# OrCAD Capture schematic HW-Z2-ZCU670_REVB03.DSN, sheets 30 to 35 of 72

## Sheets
30 030 FMC HSPC3: size Custom
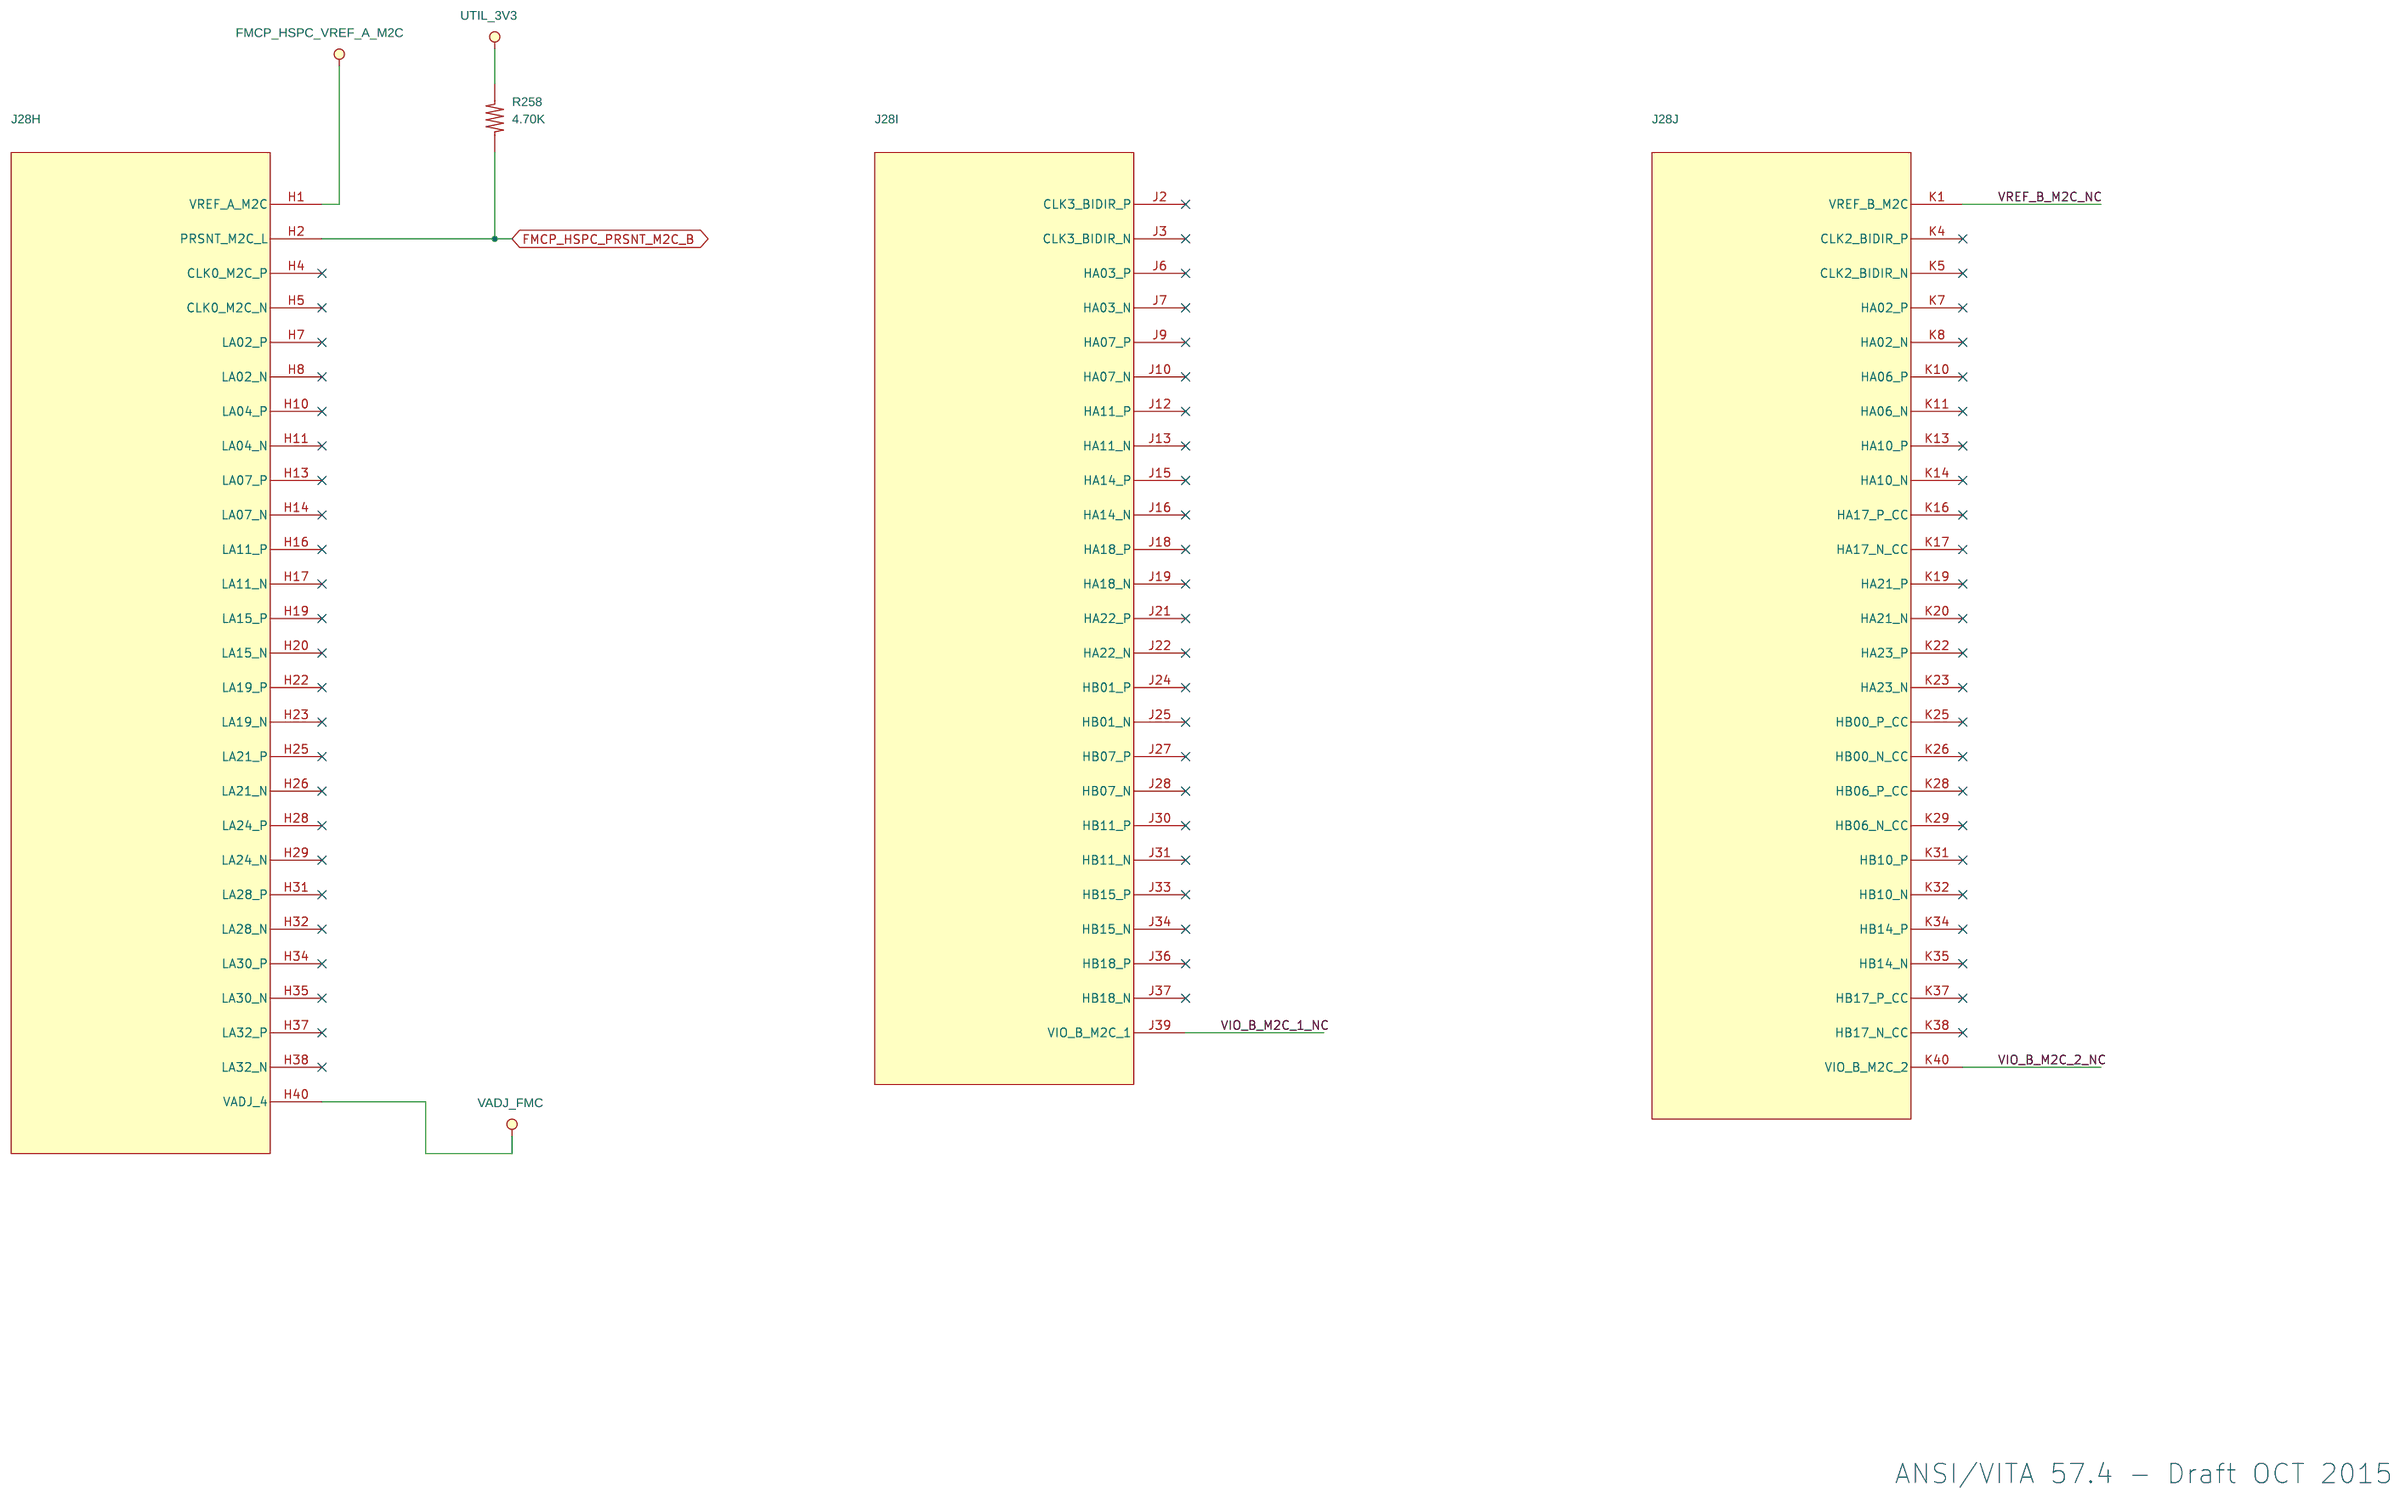
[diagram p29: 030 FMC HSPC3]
31 031 FMC HSPC4: size Custom
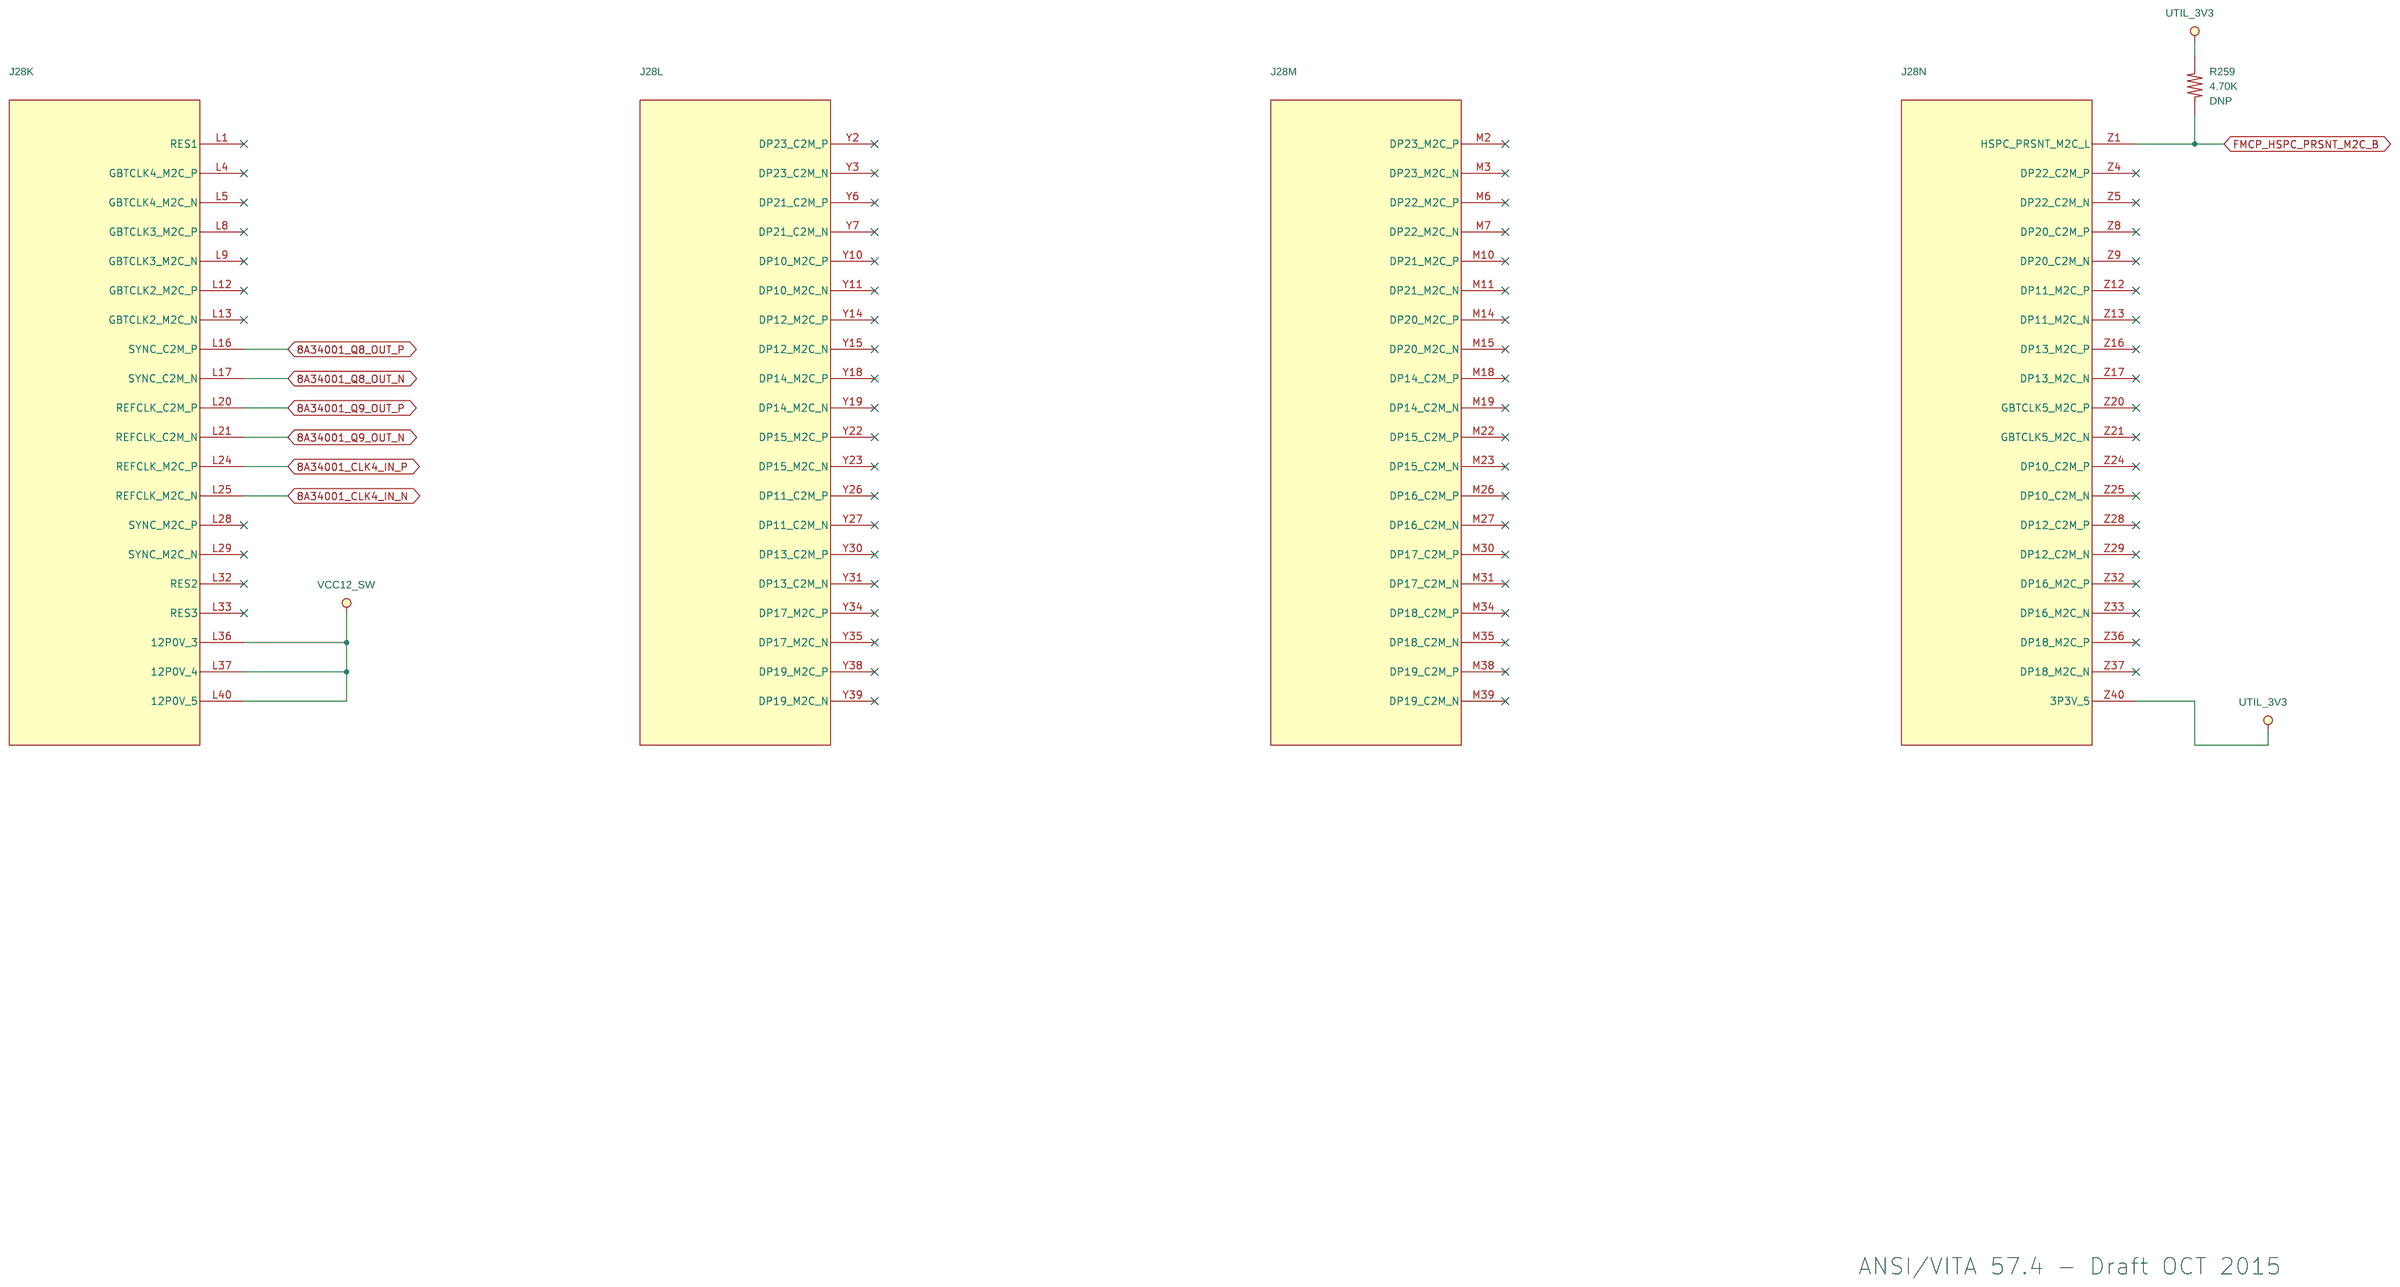
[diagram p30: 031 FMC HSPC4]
32 032 FMC HSPC5: size Custom
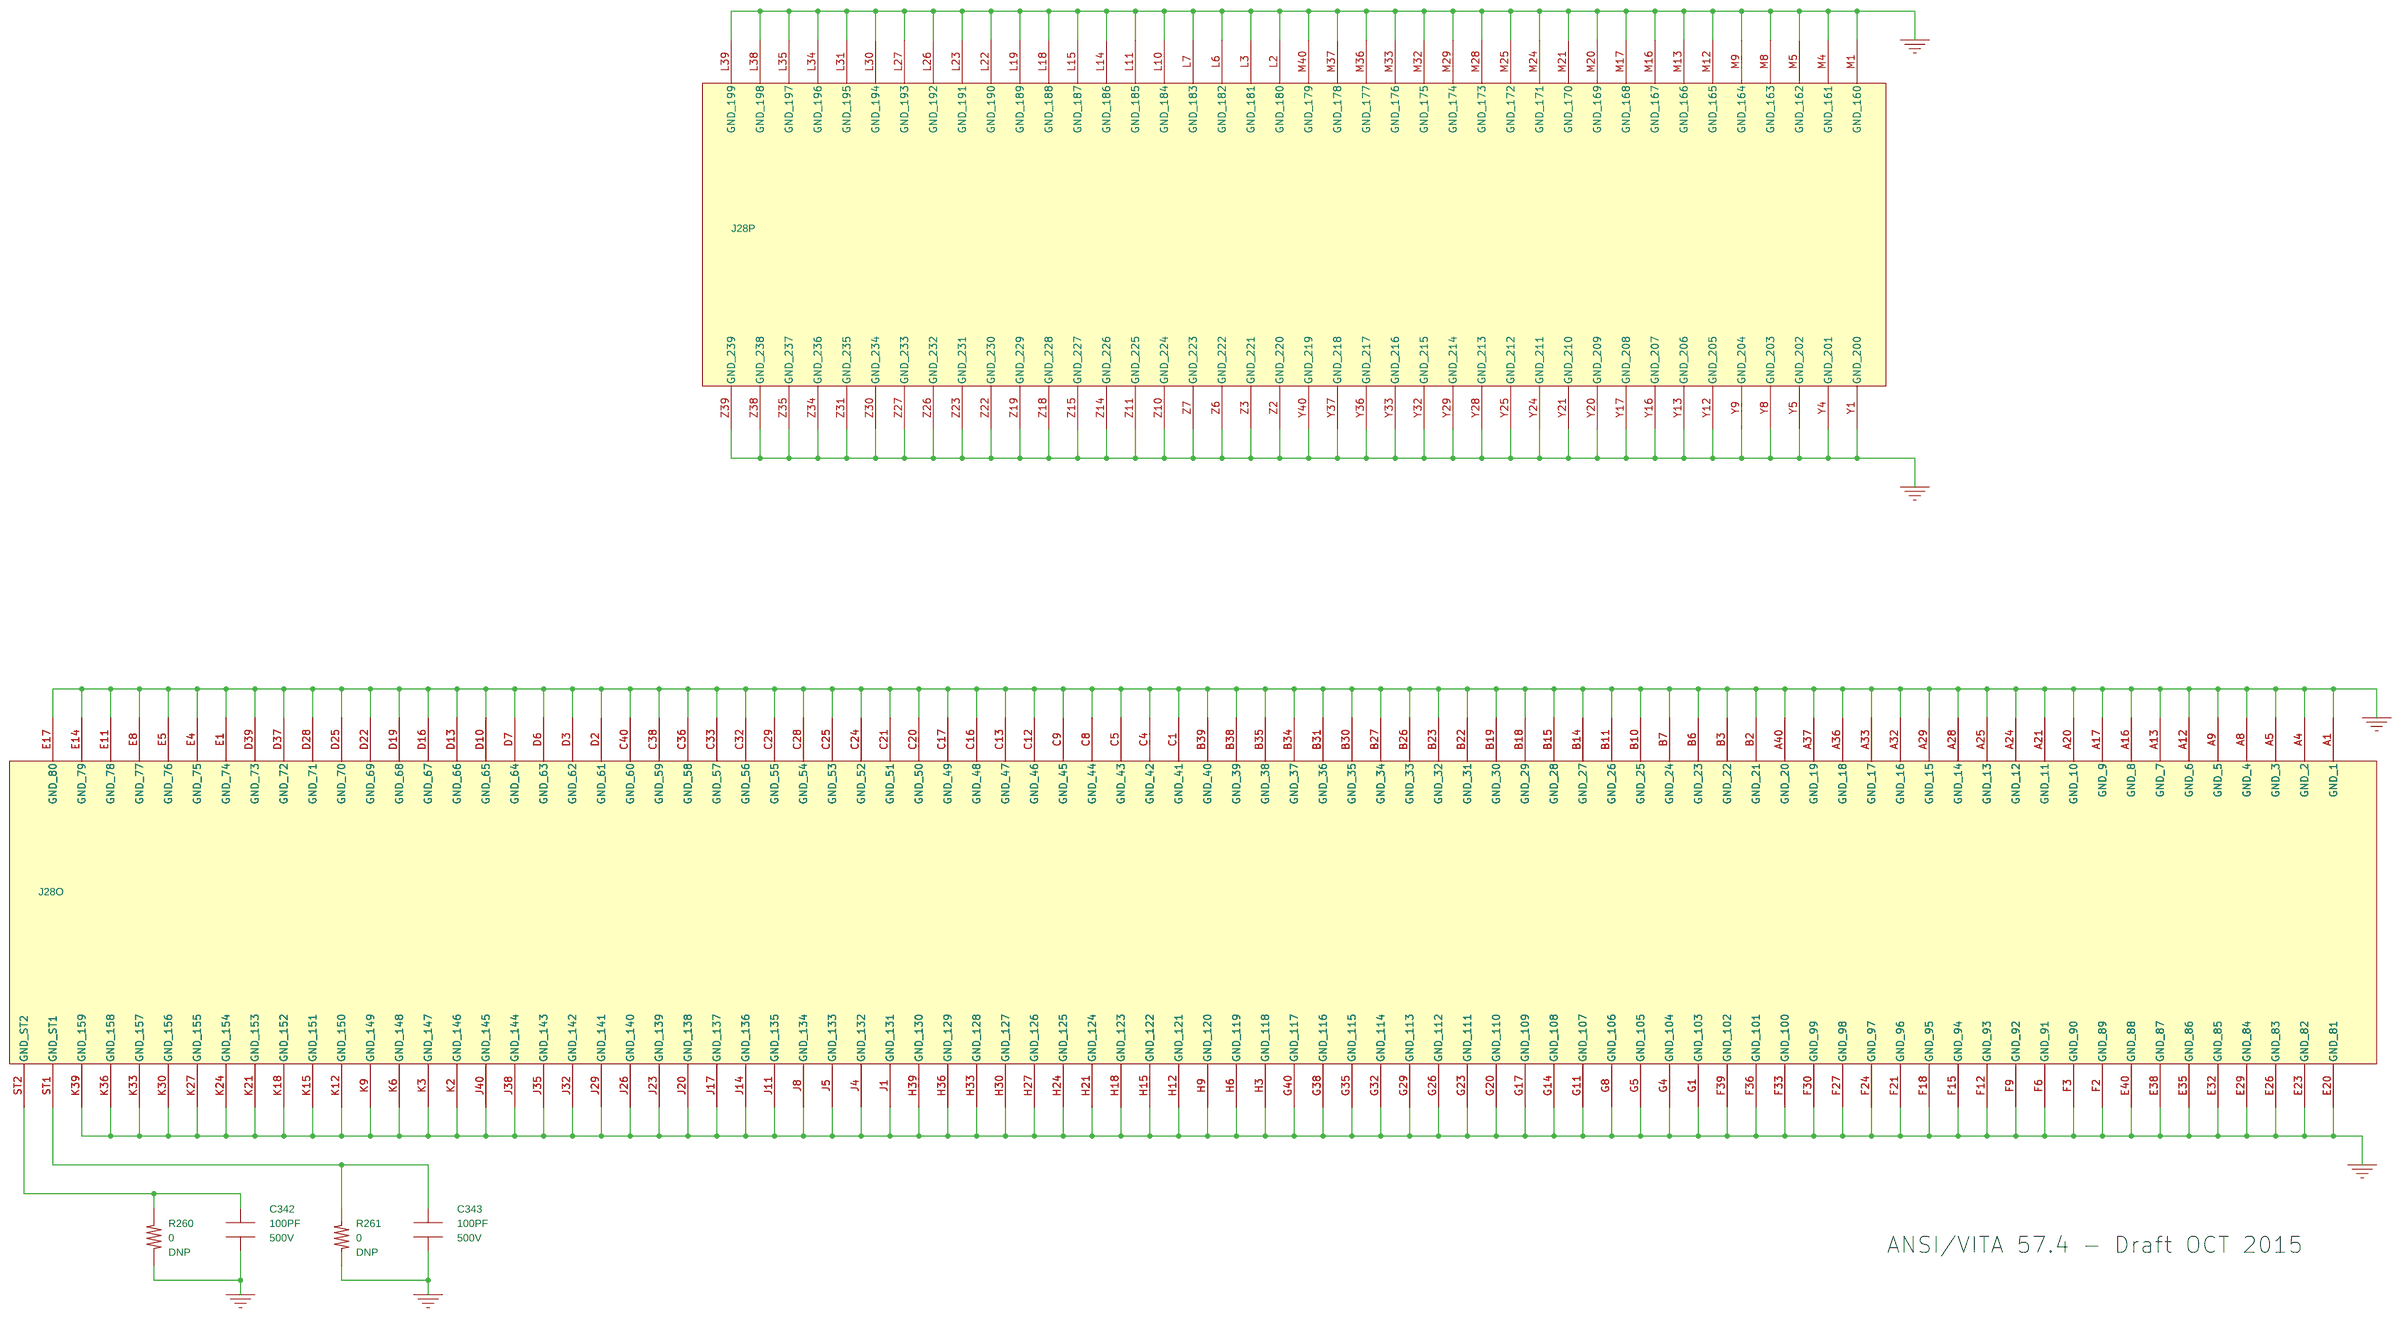
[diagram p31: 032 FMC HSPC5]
33 033 zSFP 2x2 Connector: size Custom
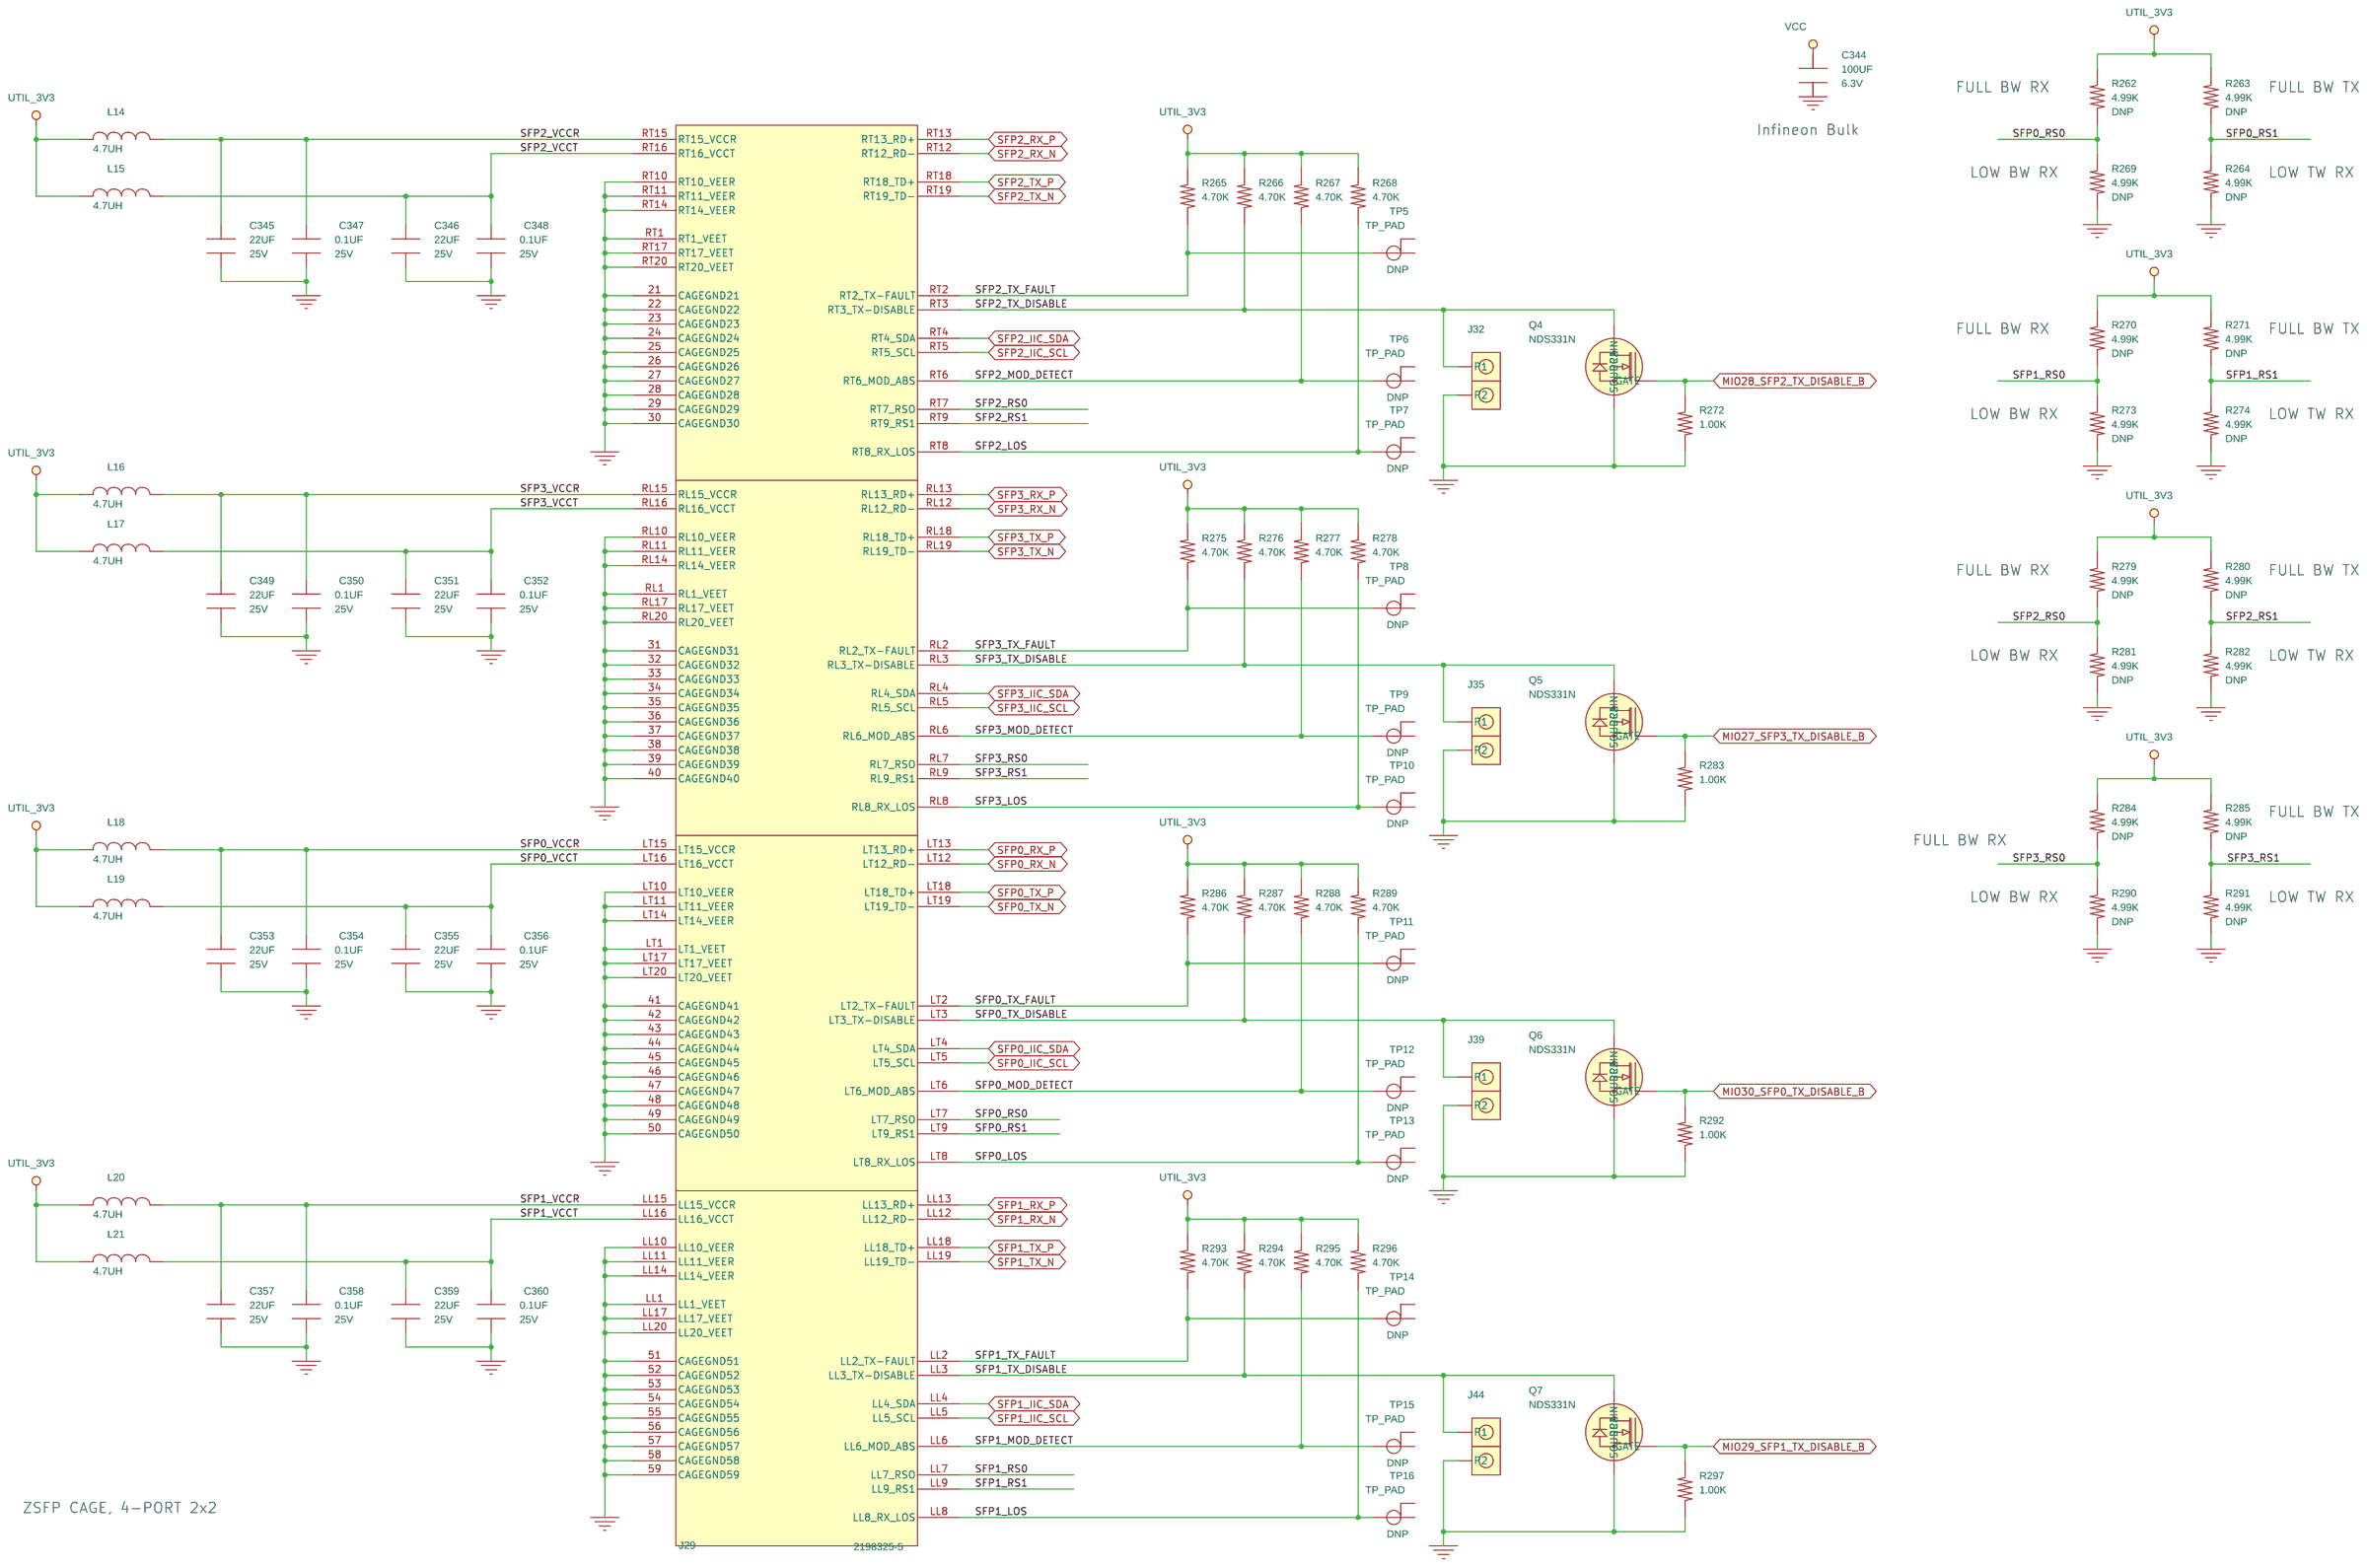
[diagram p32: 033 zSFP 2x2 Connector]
34 034 1588 eCPRI CLK 1: size Custom
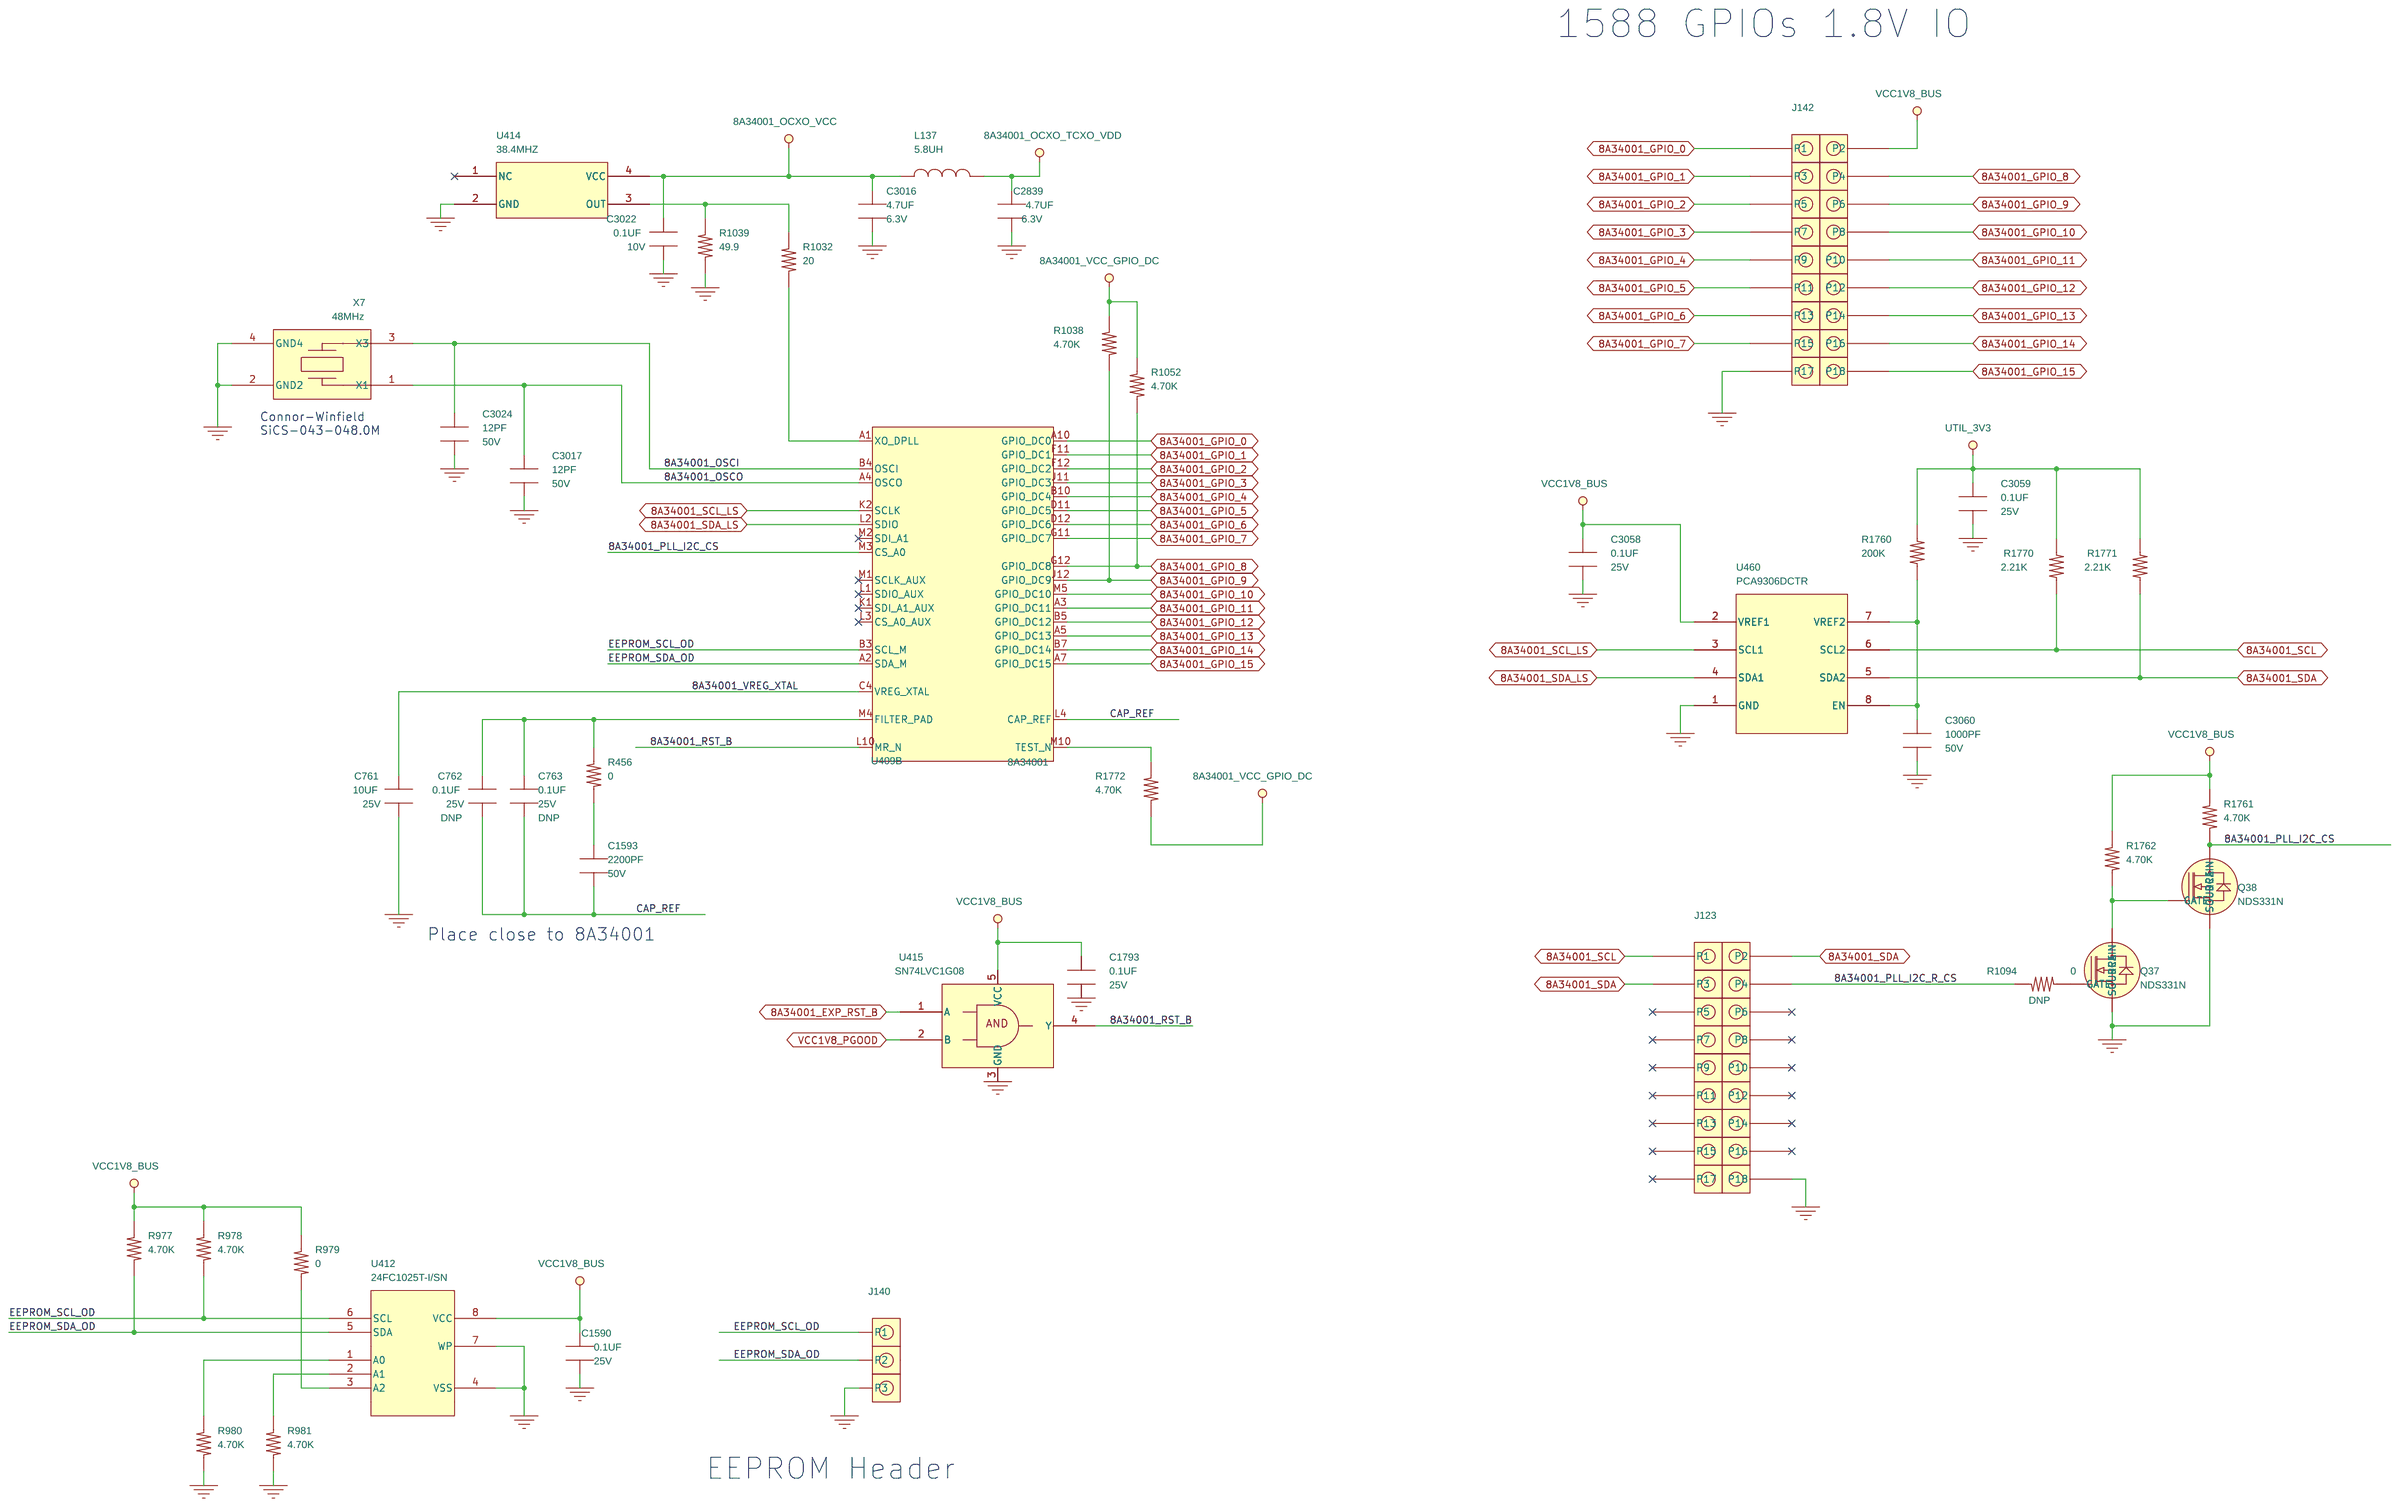
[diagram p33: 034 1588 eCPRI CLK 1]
35 036 1588 eCPRI CLK 3: size Custom
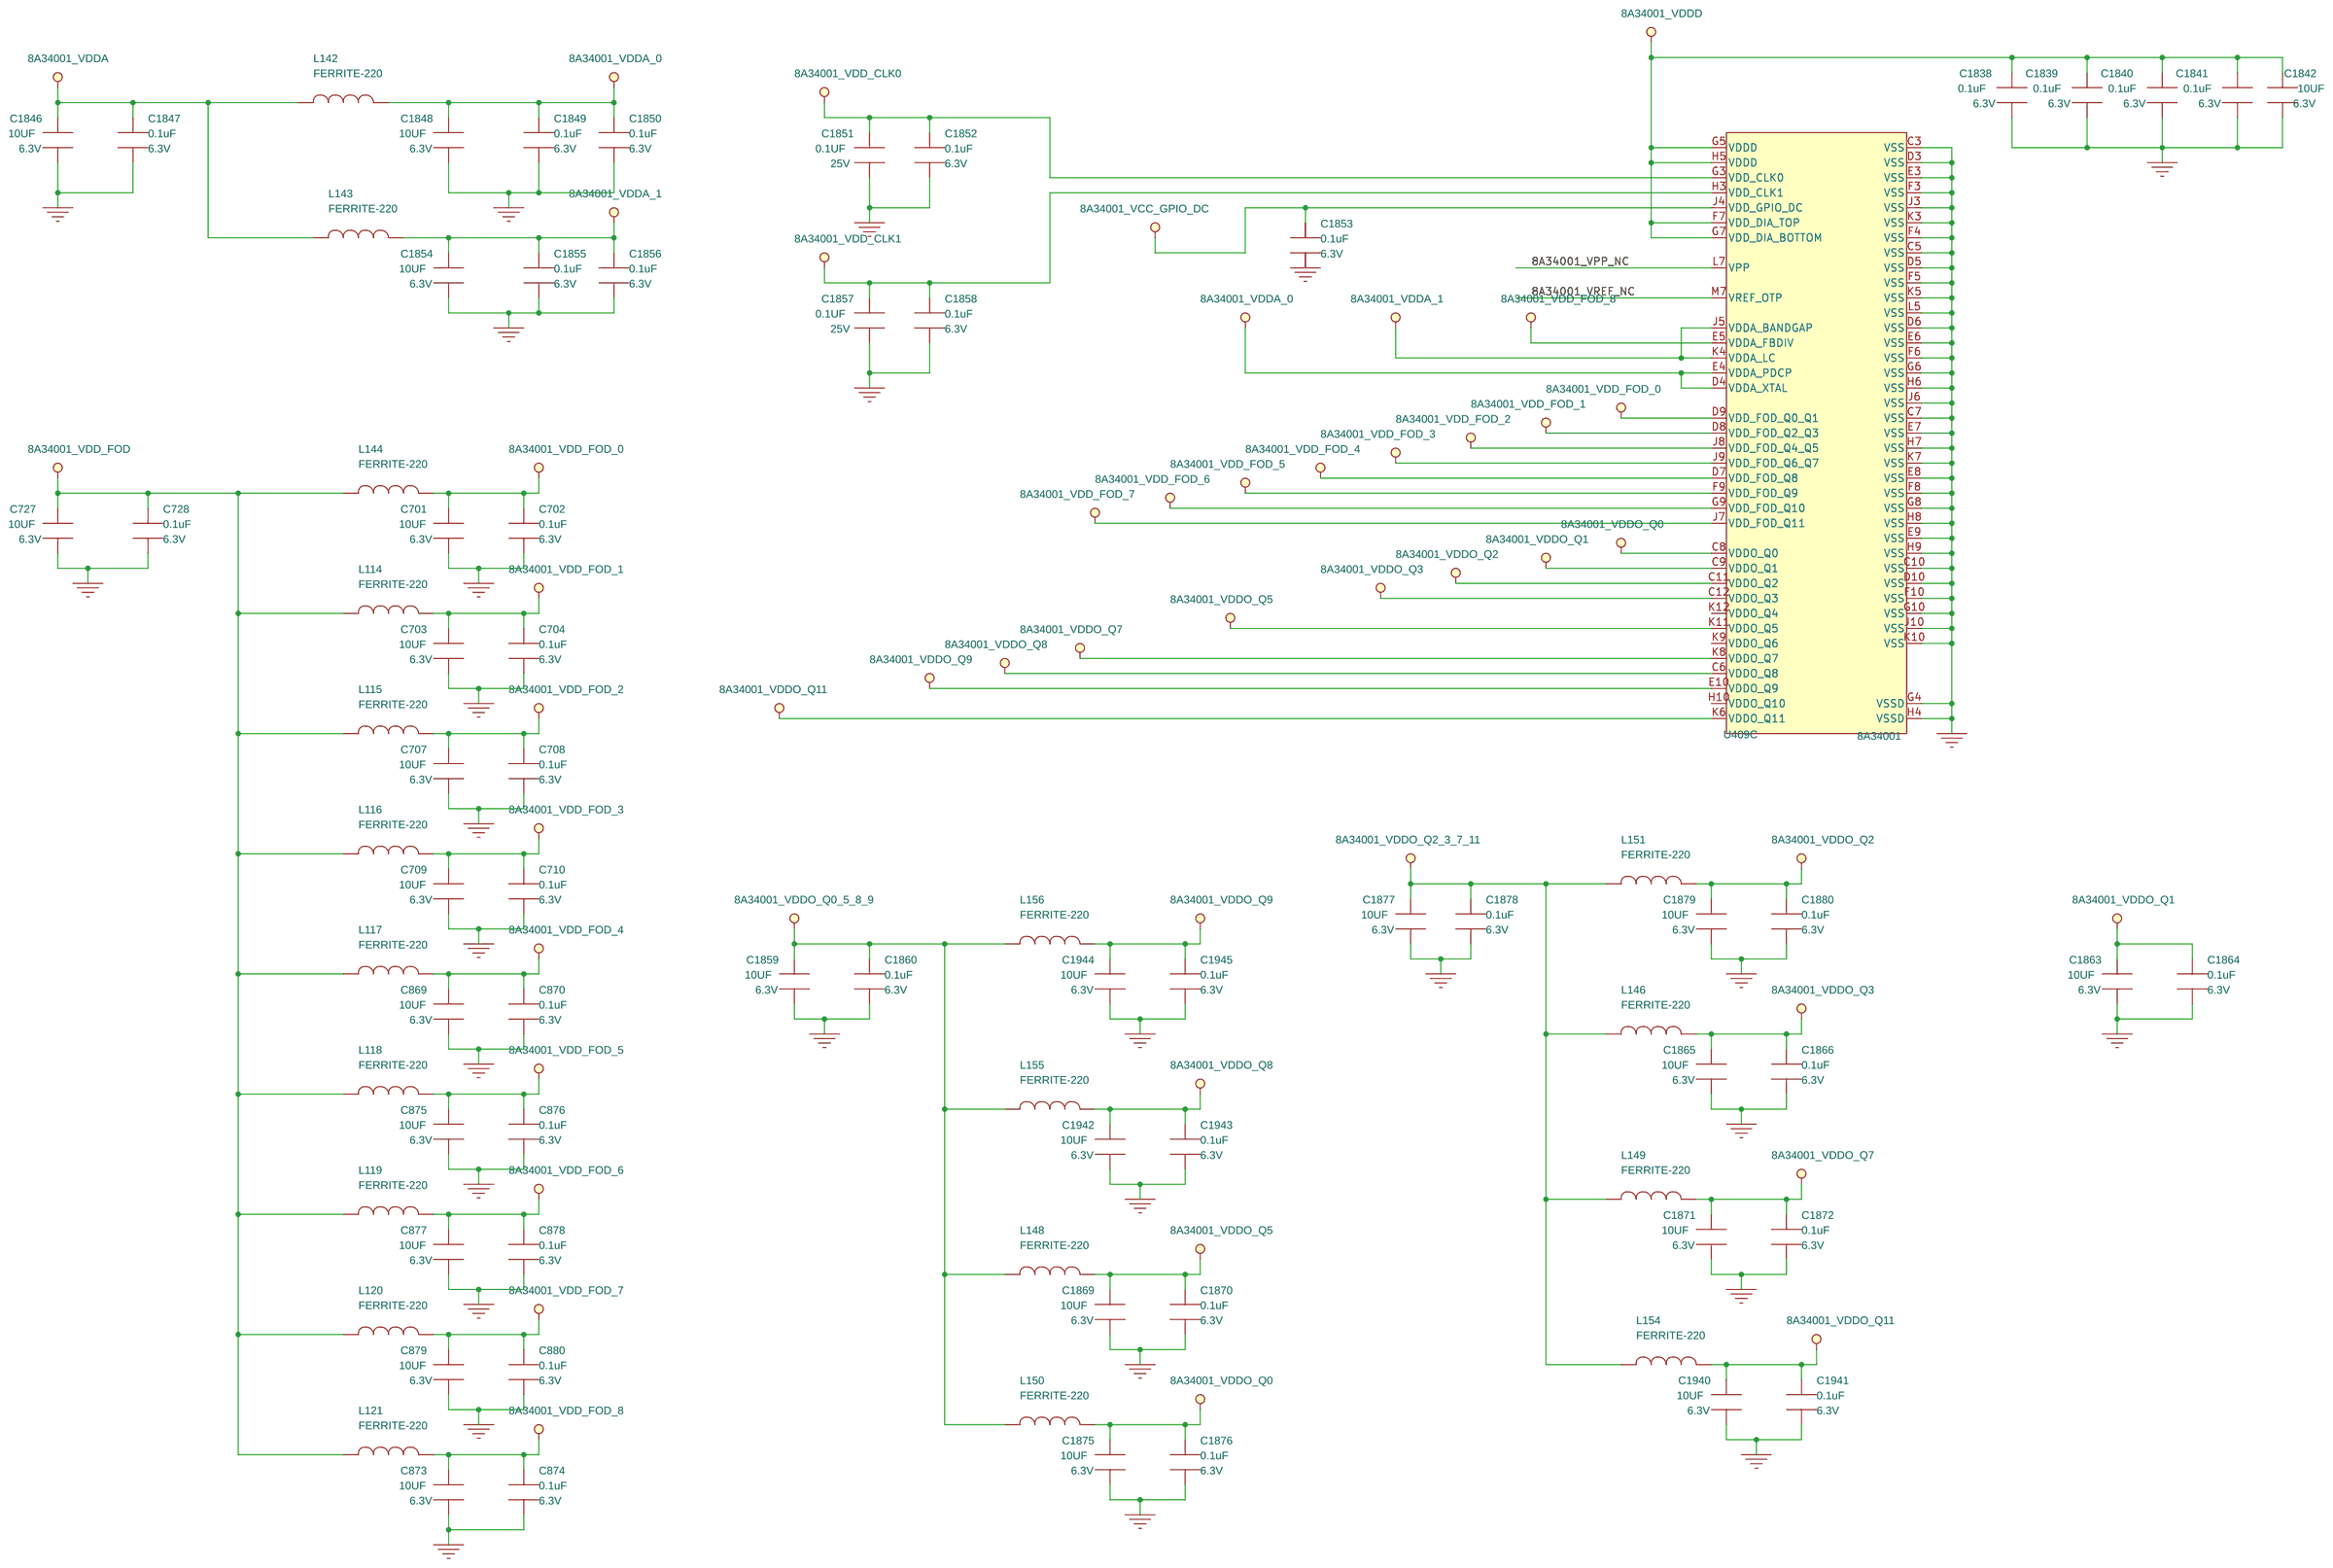
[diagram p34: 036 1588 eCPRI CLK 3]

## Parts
sheet 030 FMC HSPC3
R258  4.70K  [RESC100X50X40]
sheet 031 FMC HSPC4
J28  ASP_184329_01  [ASP_184329_01]  (sections A,B,C,D,E,F,G,H,I,J,K,L,M,N,O,P)
R259  4.70K  [RESC100X50X40]
sheet 032 FMC HSPC5
C342  100PF  [CAPC200X125X140]
C343  100PF  [CAPC200X125X140]
R260  0  [RESC100X50X40]
R261  0  [RESC100X50X40]
sheet 033 zSFP 2x2 Connector
C344  100UF  [CAPC320X160X180]
C345  22UF  [CAPC320X160X180]
C346  22UF  [CAPC320X160X180]
C347  0.1UF  [CAPC100X50X55]
C348  0.1UF  [CAPC100X50X55]
C349  22UF  [CAPC320X160X180]
C350  0.1UF  [CAPC100X50X55]
C351  22UF  [CAPC320X160X180]
C352  0.1UF  [CAPC100X50X55]
C353  22UF  [CAPC320X160X180]
C354  0.1UF  [CAPC100X50X55]
C355  22UF  [CAPC320X160X180]
C356  0.1UF  [CAPC100X50X55]
C357  22UF  [CAPC320X160X180]
C358  0.1UF  [CAPC100X50X55]
C359  22UF  [CAPC320X160X180]
C360  0.1UF  [CAPC100X50X55]
J29  2198325-5  [CON_TE_2198325_5]
J32  HDR_1X2  [HDR_1X2]
J35  HDR_1X2  [HDR_1X2]
J39  HDR_1X2  [HDR_1X2]
J44  HDR_1X2  [HDR_1X2]
L14  4.7UH  [IND_IHLP2020BZ_ER]
L15  4.7UH  [IND_IHLP2020BZ_ER]
L16  4.7UH  [IND_IHLP2020BZ_ER]
L17  4.7UH  [IND_IHLP2020BZ_ER]
L18  4.7UH  [IND_IHLP2020BZ_ER]
L19  4.7UH  [IND_IHLP2020BZ_ER]
L20  4.7UH  [IND_IHLP2020BZ_ER]
L21  4.7UH  [IND_IHLP2020BZ_ER]
Q4  NDS331N  [SOT_23]
Q5  NDS331N  [SOT_23]
Q6  NDS331N  [SOT_23]
Q7  NDS331N  [SOT_23]
R262  4.99K  [RESC100X50X40]
R263  4.99K  [RESC100X50X40]
R264  4.99K  [RESC100X50X40]
R265  4.70K  [RESC100X50X40]
R266  4.70K  [RESC100X50X40]
R267  4.70K  [RESC100X50X40]
R268  4.70K  [RESC100X50X40]
R269  4.99K  [RESC100X50X40]
R270  4.99K  [RESC100X50X40]
R271  4.99K  [RESC100X50X40]
R272  1.00K  [RESC100X50X40]
R273  4.99K  [RESC100X50X40]
R274  4.99K  [RESC100X50X40]
R275  4.70K  [RESC100X50X40]
R276  4.70K  [RESC100X50X40]
R277  4.70K  [RESC100X50X40]
R278  4.70K  [RESC100X50X40]
R279  4.99K  [RESC100X50X40]
R280  4.99K  [RESC100X50X40]
R281  4.99K  [RESC100X50X40]
R282  4.99K  [RESC100X50X40]
R283  1.00K  [RESC100X50X40]
R284  4.99K  [RESC100X50X40]
R285  4.99K  [RESC100X50X40]
R286  4.70K  [RESC100X50X40]
R287  4.70K  [RESC100X50X40]
R288  4.70K  [RESC100X50X40]
R289  4.70K  [RESC100X50X40]
R290  4.99K  [RESC100X50X40]
R291  4.99K  [RESC100X50X40]
R292  1.00K  [RESC100X50X40]
R293  4.70K  [RESC100X50X40]
R294  4.70K  [RESC100X50X40]
R295  4.70K  [RESC100X50X40]
R296  4.70K  [RESC100X50X40]
R297  1.00K  [RESC100X50X40]
TP5  TP_PAD  [TP_PAD]
TP6  TP_PAD  [TP_PAD]
TP7  TP_PAD  [TP_PAD]
TP8  TP_PAD  [TP_PAD]
TP9  TP_PAD  [TP_PAD]
TP10  TP_PAD  [TP_PAD]
TP11  TP_PAD  [TP_PAD]
TP12  TP_PAD  [TP_PAD]
TP13  TP_PAD  [TP_PAD]
TP14  TP_PAD  [TP_PAD]
TP15  TP_PAD  [TP_PAD]
TP16  TP_PAD  [TP_PAD]
sheet 034 1588 eCPRI CLK 1
C761  10UF  [CAPC320X250X220]
C762  0.1UF  [CAPC100X50X55]
C763  0.1UF  [CAPC100X50X55]
C1590  0.1UF  [CAPC100X50X55]
C1593  2200PF  [CAPC100X50X55]
C1793  0.1UF  [CAPC100X50X55]
C2839  4.7UF  [CAPC100X50X70]
C3016  4.7UF  [CAPC100X50X70]
C3017  12PF  [CAPC100X50X55]
C3022  0.1UF  [CAPC60X30X40]
C3024  12PF  [CAPC100X50X55]
C3058  0.1UF  [CAPC100X50X55]
C3059  0.1UF  [CAPC100X50X55]
C3060  1000PF  [CAPC100X50X55]
J123  0878321820  [HDR_MOLEX_87832_1820]
J140  HDR_1X3  [HDR_1X3]
J142  HDR_2X9  [HDR_2X9]
L137  5.8UH  [IND_COIL_1008AF]
Q37  NDS331N  [SOT_23]
Q38  NDS331N  [SOT_23]
R456  0  [RESC100X50X40]
R977  4.70K  [RESC100X50X40]
R978  4.70K  [RESC100X50X40]
R979  0  [RESC100X50X40]
R980  4.70K  [RESC100X50X40]
R981  4.70K  [RESC100X50X40]
R1032  20  [RESC100X50X40]
R1038  4.70K  [RESC100X50X40]
R1039  49.9  [RESC100X50X40]
R1052  4.70K  [RESC100X50X40]
R1094  0  [RESC100X50X40]
R1760  200K  [RESC100X50X40]
R1761  4.70K  [RESC100X50X40]
R1762  4.70K  [RESC100X50X40]
R1770  2.21K  [RESC100X50X40]
R1771  2.21K  [RESC100X50X40]
R1772  4.70K  [RESC100X50X40]
U412  24FC1025T-I/SN  [SOIC127P600X175_8]
U414  38.4MHZ  [OSC_RAKON_U7836LF]
U415  SN74LVC1G08  [SC70_5]
U460  PCA9306DCTR  [DCT_R_PDSO_G8]
X7  48MHz  [OSC_320X250X80_4P]
sheet 035 1588 eCPRI CLK 2
U409  8A34001  [CABGA_144P80]  (sections A,B,C)
sheet 036 1588 eCPRI CLK 3
C701  10UF  [CAPC100X50X70]
C702  0.1uF  [CAPC60X30X33]
C703  10UF  [CAPC100X50X70]
C704  0.1uF  [CAPC60X30X33]
C707  10UF  [CAPC100X50X70]
C708  0.1uF  [CAPC60X30X33]
C709  10UF  [CAPC100X50X70]
C710  0.1uF  [CAPC60X30X33]
C727  10UF  [CAPC100X50X70]
C728  0.1uF  [CAPC60X30X33]
C869  10UF  [CAPC100X50X70]
C870  0.1uF  [CAPC60X30X33]
C873  10UF  [CAPC100X50X70]
C874  0.1uF  [CAPC60X30X33]
C875  10UF  [CAPC100X50X70]
C876  0.1uF  [CAPC60X30X33]
C877  10UF  [CAPC100X50X70]
C878  0.1uF  [CAPC60X30X33]
C879  10UF  [CAPC100X50X70]
C880  0.1uF  [CAPC60X30X33]
C1838  0.1uF  [CAPC60X30X33]
C1839  0.1uF  [CAPC60X30X33]
C1840  0.1uF  [CAPC60X30X33]
C1841  0.1uF  [CAPC60X30X33]
C1842  10UF  [CAPC100X50X70]
C1846  10UF  [CAPC100X50X70]
C1847  0.1uF  [CAPC60X30X33]
C1848  10UF  [CAPC100X50X70]
C1849  0.1uF  [CAPC60X30X33]
C1850  0.1uF  [CAPC60X30X33]
C1851  0.1UF  [CAPC100X50X55]
C1852  0.1uF  [CAPC60X30X33]
C1853  0.1uF  [CAPC60X30X33]
C1854  10UF  [CAPC100X50X70]
C1855  0.1uF  [CAPC60X30X33]
C1856  0.1uF  [CAPC60X30X33]
C1857  0.1UF  [CAPC100X50X55]
C1858  0.1uF  [CAPC60X30X33]
C1859  10UF  [CAPC100X50X70]
C1860  0.1uF  [CAPC60X30X33]
C1863  10UF  [CAPC100X50X70]
C1864  0.1uF  [CAPC60X30X33]
C1865  10UF  [CAPC100X50X70]
C1866  0.1uF  [CAPC60X30X33]
C1869  10UF  [CAPC100X50X70]
C1870  0.1uF  [CAPC60X30X33]
C1871  10UF  [CAPC100X50X70]
C1872  0.1uF  [CAPC60X30X33]
C1875  10UF  [CAPC100X50X70]
C1876  0.1uF  [CAPC60X30X33]
C1877  10UF  [CAPC100X50X70]
C1878  0.1uF  [CAPC60X30X33]
C1879  10UF  [CAPC100X50X70]
C1880  0.1uF  [CAPC60X30X33]
C1940  10UF  [CAPC100X50X70]
C1941  0.1uF  [CAPC60X30X33]
C1942  10UF  [CAPC100X50X70]
C1943  0.1uF  [CAPC60X30X33]
C1944  10UF  [CAPC100X50X70]
C1945  0.1uF  [CAPC60X30X33]
L114  FERRITE-220  [INDC100X50X55]
L115  FERRITE-220  [INDC100X50X55]
L116  FERRITE-220  [INDC100X50X55]
L117  FERRITE-220  [INDC100X50X55]
L118  FERRITE-220  [INDC100X50X55]
L119  FERRITE-220  [INDC100X50X55]
L120  FERRITE-220  [INDC100X50X55]
L121  FERRITE-220  [INDC100X50X55]
L142  FERRITE-220  [INDC100X50X55]
L143  FERRITE-220  [INDC100X50X55]
L144  FERRITE-220  [INDC100X50X55]
L146  FERRITE-220  [INDC100X50X55]
L148  FERRITE-220  [INDC100X50X55]
L149  FERRITE-220  [INDC100X50X55]
L150  FERRITE-220  [INDC100X50X55]
L151  FERRITE-220  [INDC100X50X55]
L154  FERRITE-220  [INDC100X50X55]
L155  FERRITE-220  [INDC100X50X55]
L156  FERRITE-220  [INDC100X50X55]

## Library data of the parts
R258 R265-R268 R275-R278 R286-R289 R293-R296 R977 R978 R980 R981 R1038 R1052 R1761 R1762 R1772 = RES: Res 4K7 1% 1/16W 100PPM 50V 0402; ALT_SYMBOLS: RESC100X50X40RND; Agile Part Number: RES-00035-01; Barcode: 200067; CIP Link: http://xsjbrdwin1/CIP-E/Component/Index/All?pn=200067; OWNER: 3670; PRICE: 0.01; Part Type: SMT - 1%; PartType: SMT - 1%; Power: 1/16W; ROHS: Yes; Rated Power: 1/16W; Tolerance: 1%; primarykey: 128
J28 = ASP_184329_01: Conn Rcpt Female Vert 560 Pos 14x40 1.27mm P Black SMT; Agile Part Number: CON-00190-01; Barcode: 400137; CIP Link: http://xsjbrdwin1/CIP-E/Component/Index/All?pn=400137; OWNER: 3709; PRICE: 0; Part Type: HEADER; PartType: HEADER; Pins: 560PINS; Pitch: 1.27mm; ROHS: Yes
R259 = RES: Res 4K7 1% 1/16W 100PPM 50V 0402; ALT_SYMBOLS: RESC100X50X40RND; ASSEMBLY_OPTIONS: DNP; Agile Part Number: RES-00035-01; Barcode: 200067; CIP Link: http://xsjbrdwin1/CIP-E/Component/Index/All?pn=200067; OWNER: 3670; PRICE: 0.01; Part Type: SMT - 1%; PartType: SMT - 1%; Power: 1/16W; ROHS: Yes; Rated Power: 1/16W; Tolerance: 1%; primarykey: 128
C342 C343 = CAP_NP: Cap Cer 100pF 5% 500V C0G 0805; ALT_SYMBOLS: CAPC200X125X140RND; Agile Part Number: CAP-00072-01; CIP Link: http://xsjbrdwin1/CIP-E/Component/Index/All?pn=100047; Dielectric Type: NP0; OWNER: 3709; PRICE: 0.08; Part Type: CERAMIC; PartType: CERAMIC; ROHS: Yes; Tolerance: 5%; Voltage: 500V; barcode: 100047
R260 R261 = RES: Res 0R 50mR 1A 0402; ALT_SYMBOLS: RESC100X50X40RND; ASSEMBLY_OPTIONS: DNP; Agile Part Number: RES-00010-01; Barcode: 200012; CIP Link: http://xsjbrdwin1/CIP-E/Component/Index/All?pn=200012; OWNER: 3709; Part Type: SMT - 5%; PartType: SMT - DNP; Power: DNP; ROHS: Yes; Tolerance: 5%; primarykey: 73
C344 = CAP_NP: Cap Cer 100uF 20% 6.3V X5R 1206; ALT_SYMBOLS: 1206; Agile Part Number: CAP-00061-01; CIP Link: http://xsjbrdwin1/CIP-E/Component/Index/All?pn=100029; Dielectric Type: X5R; OWNER: 3709; PRICE: 0.41; Part Type: CERAMIC; PartType: CERAMIC; ROHS: Yes; Tolerance: 20%; Voltage: 6.3V; barcode: 100029
C345 C346 C349 C351 C353 C355 C357 C359 = CAP_NP: Cap Cer 22uF 10% 25V X5R 1206; ALT_SYMBOLS: CAPC320X160X180RND; Agile Part Number: CAP-00058-01; CIP Link: http://xsjbrdwin1/CIP-E/Component/Index/All?pn=100026; Dielectric Type: X5R; OWNER: 3709; PRICE: 0.17; Part Type: CERAMIC; PartType: CERAMIC; ROHS: Yes; Tolerance: 10%; Voltage: 25V; barcode: 100026
C347 C348 C350 C352 C354 C356 C358 C360 C1793 C3058 C3059 = CAP_NP: Cap Cer 100nF 10% 25V X5R 0402; ALT_SYMBOLS: CAPC100X50X55RND; Agile Part Number: CAP-00068-01; CIP Link: http://xsjbrdwin1/CIP-E/Component/Index/All?pn=100040; Dielectric Type: X5R; OWNER: 4001; PRICE: 0.01; Part Type: CERAMIC; PartType: CERAMIC; ROHS: Yes; Tolerance: 10%; Voltage: 25V; barcode: 100040
J29 = 2198325-5: Conn Cage Rcpt zSFP+ RA 2x2 Stacked Black TH; Agile Part Number: CON-00299-01; Barcode: 40000015; CIP Link: http://xsjbrdwin1/CIP-E/Component/Index/All?pn=40000015; Number of Pins: 80 (20 x 4); Part Type: Connectors, Interconnects\Through Hole, Right Angle
J32 J35 J39 J44 = HDR_1X2: Conn Hdr Male Vert 2 Pos 1x2 2.54mm P Black TH; Agile Part Number: CON-00037-01; Barcode: 390102; CIP Link: http://xsjbrdwin1/CIP-E/Component/Index/All?pn=390102; OWNER: 4001; PRICE: 0.03; Part Type: HEADER; PartType: HEADER; Pins: 2PINS; Pitch: 0.100; ROHS: Yes
L14-L21 = IND: Ind 4.7uH 20% 3.2A Irms 3.0A Isat 81.3mR 5.49x5.18mm SMT Shielded; Agile Part Number: IND-00167-01; Barcode: 500072; CIP Link: http://xsjbrdwin1/CIP-E/Component/Index/All?pn=500072; OWNER: 3709; PRICE: 1.08; Part Type: POWER INDUCTOR; PartType: POWER INDUCTOR; ROHS: Yes; Tolerance: 20%
Q4-Q7 Q37 Q38 = FET-3PIN: MOSFET N-Ch 20V 1.3A 160mR SSOT-3; Agile Part Number: TRN-00012-01; Barcode: 500100; CIP Link: http://xsjbrdwin1/CIP-E/Component/Index/All?pn=500100; OWNER: 4001; PRICE: 0.12; Part Type: FET; PartType: FET; Power: 460MW; ROHS: Yes; Rated Power: 460MW; Rated Voltage: 20V
R262-R264 R269-R271 R273 R274 R279-R282 R284 R285 R290 R291 = RES: Res 4K99 1% 1/16W 100PPM 50V 0402; ALT_SYMBOLS: RESC100X50X40RND; ASSEMBLY_OPTIONS: DNP; Agile Part Number: RES-00004-01; Barcode: 200072; CIP Link: http://xsjbrdwin1/CIP-E/Component/Index/All?pn=200072; OWNER: 3709; PRICE: 0; Part Type: SMT - 1%; PartType: SMT - DNP; Power: DNP; ROHS: Yes; Rated Power: 1/16W; Tolerance: 1%; primarykey: 73
R272 R283 R292 R297 = RES: Res 1K 1% 1/16W 100PPM 50V 0402; ALT_SYMBOLS: RESC100X50X40RND; Agile Part Number: RES-00027-01; Barcode: 200098; CIP Link: http://xsjbrdwin1/CIP-E/Component/Index/All?pn=200098; OWNER: 4001; PRICE: 0; Part Type: SMT - 1%; PartType: SMT - 1%; Power: 1/16W; ROHS: Yes; Rated Power: 1/16W; Tolerance: 1%; primarykey: 7
TP5-TP16 = TP: TEST POINT 24mil SM pad; ASSEMBLY_OPTIONS: DNP; Barcode: 96000010; CIP Link: http://xsjbrdwin1/CIP-E/Component/Index/All?pn=96000010; OWNER: 3709; Part Type: Unassigned Part Type; PartType: TEST POINT; Pins: 1PIN; ROHS: Yes
C761 = CAP_NP: Cap Cer 10uF 10% 25V X5R 1210; ALT_SYMBOLS: CAPC320X250X220RND; Agile Part Number: CAP-00113-01; Barcode: 100123; CIP Link: http://xsjbrdwin1/CIP-E/Component/Index/All?pn=100123; Dielectric Type: X5R; Part Type: CERAMIC; Tolerance: 10%; Voltage: 25V
C762 C763 = CAP_NP: Cap Cer 100nF 10% 25V X5R 0402; ALT_SYMBOLS: CAPC100X50X55RND; ASSEMBLY_OPTIONS: DNP; Agile Part Number: CAP-00068-01; Barcode: 100040; CIP Link: http://xsjbrdwin1/CIP-E/Component/Index/All?pn=100040; Dielectric Type: X5R; Part Type: CERAMIC; Tolerance: 10%; Voltage: 25V
C1590 C1851 C1857 = CAP_NP: Cap Cer 100nF 10% 25V X5R 0402; ALT_SYMBOLS: CAPC100X50X55RND; Agile Part Number: CAP-00068-01; Barcode: 100040; CIP Link: http://xsjbrdwin1/CIP-E/Component/Index/All?pn=100040; Dielectric Type: X5R; Part Type: CERAMIC; Tolerance: 10%; Voltage: 25V
C1593 = CAP_NP: Cap Cer 2.2nF 10% 50V X7R 0402; ALT_SYMBOLS: CAPC100X50X55RND; Agile Part Number: CAP-00030-01; Barcode: 100095; CIP Link: http://xsjbrdwin1/CIP-E/Component/Index/All?pn=100095; Dielectric Type: X7R; Part Type: CERAMIC; Tolerance: 10%; Voltage: 50V
C2839 = CAP_NP: Cap Cer 4.7uF 20% 6.3V X6S 0402; ALT_SYMBOLS: CAPC100X50X70RND; Agile Part Number: CAP-00023-01; Barcode: 100230; CIP Link: http://xsjbrdwin1/CIP-E/Component/Index/All?pn=100230; Dielectric Type: X6S; Part Type: CERAMIC; Tolerance: 20%; Voltage: 6.3V
C3016 = CAP_NP: Cap Cer 4.7uF 20% 6.3V X6S 0402; ALT_SYMBOLS: CAPC100X50X70RND; Agile Part Number: CAP-00023-01; CIP Link: http://xsjbrdwin1/CIP-E/Component/Index/All?pn=100230; Dielectric Type: X6S; OWNER: 6176; PRICE: 0.06; Part Type: CERAMIC; PartType: CERAMIC; ROHS: Yes; Tolerance: 20%; Voltage: 6.3V; barcode: 100230
C3017 C3024 = CAP_NP: Cap Cer 12pF 5% 50V C0G 0402; ALT_SYMBOLS: (0402,C402-25,CAPC100X50X55L25NRND,CAPC100X50X55L30NRND,CAPC100X50X55L30N); Agile Part Number: CAP-00095-01; Barcode: 100092; CIP Link: http://xsjbrdwin1/CIP-E/Component/Index/All?pn=100092; Dielectric Type: NP0; Part Type: CERAMIC; Tolerance: 5%; Voltage: 50V
C3022 = CAP_NP: CAP CER 0.1UF 10V X7S 0201; ALT_SYMBOLS: CAPC60X30X40RND; Agile Part Number: CAP-00253-01; Barcode: 100334; CIP Link: http://xsjbrdwin1/CIP-E/Component/Index/All?pn=100334; Dielectric Type: X7S; Part Type: CERAMIC; Tolerance: 10%; Voltage: 10V
C3060 = CAP_NP: Cap Cer 1nF 10% 50V X7R 0402; ALT_SYMBOLS: CAPC100X50X55RND; Agile Part Number: CAP-00036-01; CIP Link: http://xsjbrdwin1/CIP-E/Component/Index/All?pn=100013; Dielectric Type: X7R; OWNER: 3709; PRICE: 0; Part Type: CERAMIC; PartType: CERAMIC; ROHS: Yes; Tolerance: 10%; Voltage: 50V; barcode: 100013
J123 = HDR_2X9: Conn Hdr Male Vert 18 Pos 2x9 2mm P Black SMT Shrouded; Agile Part Number: CON-00300-01; Barcode: 40000021; CIP Link: http://xsjbrdwin1/CIP-E/Component/Index/All?pn=40000021; Number of Pins: 18; Part Type: Unassigned Part Type; Pitch: 0.079" (2.00mm)
J140 = HDR_1X3: Conn Hdr Vert 3 Pos 1x3 2.54mm P Black TH; Agile Part Number: CON-00038-01; Barcode: 390103; CIP Link: http://xsjbrdwin1/CIP-E/Component/Index/All?pn=390103; Part Type: HEADER; Pitch: 0.100; ROHS: Yes
J142 = HDR_2X9: CONN HEADER VERT 18POS 2.54MM; Agile Part Number: CON-00079-01; Barcode: 390209; CIP Link: http://xsjbrdwin1/CIP-E/Component/Index/All?pn=390209; Part Type: HEADER; Pitch: 0.100
L137 = IND: Ind 5.8uH 5% 750mA Irms 550mA Isat 280mR 1008; Agile Part Number: IND-00198-01; Barcode: 30000037; CIP Link: http://xsjbrdwin1/CIP-E/Component/Index/All?pn=30000037; Part Type: POWER INDUCTOR; Rated Current: 750 mA; Tolerance: 5 %
R456 R979 = RES: Res 0R 50mR 1A 0402; ALT_SYMBOLS: RESC100X50X40RND; Agile Part Number: RES-00010-01; Barcode: 200012; CIP Link: http://xsjbrdwin1/CIP-E/Component/Index/All?pn=200012; Part Type: SMT - 5%; Tolerance: 5%
R1032 = RES: Res 20R 1% 1/16W 100PPM 50V 0402; ALT_SYMBOLS: RESC100X50X40RND; Agile Part Number: RES-00033-01; Barcode: 200119; CIP Link: http://xsjbrdwin1/CIP-E/Component/Index/All?pn=200119; OWNER: 4001; PRICE: 0; Part Type: SMT - 1%; PartType: SMT - 1%; Power: 1/16W; ROHS: Yes; Rated Power: 1/16W; Tolerance: 1%; primarykey: 78
R1039 = RES: Res 49R9 1% 1/16W 100PPM 50V 0402; ALT_SYMBOLS: RESC100X50X40RND; Agile Part Number: RES-00104-01; Barcode: 200073; CIP Link: http://xsjbrdwin1/CIP-E/Component/Index/All?pn=200073; Part Type: SMT - 1%; Rated Power: 1/16W; Tolerance: 1%
R1094 = RES: Res 0R 50mR 1A 0402; ALT_SYMBOLS: RESC100X50X40RND; ASSEMBLY_OPTIONS: DNP; Agile Part Number: RES-00010-01; Barcode: 200012; CIP Link: http://xsjbrdwin1/CIP-E/Component/Index/All?pn=200012; Part Type: SMT - 5%; Tolerance: 5%
R1760 = RES: Res 200K 1% 1/16W 100PPM 50V 0402; Agile Part Number: RES-00078-01; Barcode: 200041; CIP Link: http://xsjbrdwin1/CIP-E/Component/Index/All?pn=200041; OWNER: 10460; PRICE: 0; Part Type: SMT - 1%; PartType: SMT - 1%; Power: 1/10W; ROHS: Yes; Rated Power: 1/10W; Tolerance: 1%; primarykey: 98
R1770 R1771 = RES: Res 2K21 1% 1/16W 100PPM 50V 0402; ALT_SYMBOLS: (0402,C402-25,RESC100X50X40L25NRND); Agile Part Number: RES-00023-01; Barcode: 200163; CIP Link: http://xsjbrdwin1/CIP-E/Component/Index/All?pn=200163; OWNER: 3709; PRICE: 0; Part Type: SMT - 1%; PartType: SMT - 1%; Power: 1/10W; ROHS: Yes; Rated Power: 1/16W; Tolerance: 1%; primarykey: 254
U412 = 24LC64: IC EEPROM 1Mb 128Kbx8 1MHz 1.8-5.5V SOIC-8; Agile Part Number: ICS-00515-01; Barcode: 50000044; CIP Link: http://xsjbrdwin1/CIP-E/Component/Index/All?pn=50000044; Part Type: Unassigned Part Type; Supply Voltage: 1.8V ~ 5.5V
U414 = U7836LF: Osc OCXO 38.4MHz 3.3V 20PPB 50pF 9.7x7.5mm SMT CMOS; Agile Part Number: OSC-00054-01; Barcode: 60000009; CIP Link: http://xsjbrdwin1/CIP-E/Component/Index/All?pn=60000009; Part Type: OSCILLATOR; RoHS: YES; Supply Voltage: 3.3V
U415 = AND_GATE_SINGLE: IC AND Single 2-In 5V 50mA 3.6nSec SC70-5; Agile Part Number: ICS-00094-01; Barcode: 500077; CIP Link: http://xsjbrdwin1/CIP-E/Component/Index/All?pn=500077; Part Type: LOGIC
U460 = PCA9306DCTR: IC Lvl Trans Dual Bidir I2C/SM Bus 1.2-5.5V SSOP-8; Agile Part Number: ICS-00172-01; Barcode: 500219; CIP Link: http://xsjbrdwin1/CIP-E/Component/Index/All?pn=500219; Family: LEVEL TRANSLATOR; Part Type: LEVEL TRANSLATOR; ROHS: Yes
X7 = FA-238A_XTAL: CRYSTAL 48.0000MHZ 8PF SMD; Barcode: 60000024; CIP Link: http://xsjbrdwin1/CIP-E/Component/Index/All?pn=60000024; Frequency Stability: 25ppm; Frequency Tolerance: 15ppm; Load Capacitance: 8pF; Part Type: CRYSTAL
U409 = 8A34001: IC Synch Man Unit 8-Ch 24 LVCMOS Outs CABGA-144; Agile Part Number: ICS-00510-01; Barcode: 50000042; CIP Link: http://xsjbrdwin1/CIP-E/Component/Index/All?pn=50000042; Part Type: Unassigned Part Type
C701 C703 C707 C709 C727 C869 C873 C875 C877 C879 C1842 C1846 C1848 C1854 C1859 C1863 C1865 C1869 C1871 C1875 C1877 C1879 C1940 C1942 C1944 = CAP_NP: Cap Cer 10uF 20%  6.3V X6S 0402; ALT_SYMBOLS: CAPC100X50X55RND; Agile Part Number: CAP-00035-01; Barcode: 100268; CIP Link: http://xsjbrdwin1/CIP-E/Component/Index/All?pn=100268; Dielectric Type: X6S; Part Type: CERAMIC; Tolerance: 20%; Voltage: 6.3V
C702 C704 C708 C710 C728 C870 C874 C876 C878 C880 C1838-C1841 C1847 C1849 C1850 C1852 C1853 C1855 C1856 C1858 C1860 C1864 C1866 C1870 C1872 C1876 C1878 C1880 C1941 C1943 C1945 = CAP_NP: Cap Cer 100nF 10% 6.3V X5R 0201; ALT_SYMBOLS: CAPC60X30X33RND; Agile Part Number: CAP-00280-01; Barcode: 10000016; CIP Link: http://xsjbrdwin1/CIP-E/Component/Index/All?pn=10000016; Part Type: --\-\0201 (0603 Metric); Tolerance: 10%; Voltage: 6.3V
L114-L121 L142-L144 L146 L148-L151 L154-L156 = IND: Bead 220R 25% 250mA 1R 0402; Agile Part Number: FLT-00023-01; Barcode: 96000007; CIP Link: http://xsjbrdwin1/CIP-E/Component/Index/All?pn=96000007; Part Type: Unassigned Part Type

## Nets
GND: C342.2 C343.2 C344.2 C345.2 C346.2 C347.2 C348.2 C349.2 C350.2 C351.2 C352.2 C353.2 C354.2 C355.2 C356.2 C357.2 C358.2 C359.2 C360.2 C701.2 C702.2 C703.2 C704.2 C707.2 C708.2 C709.2 C710.2 C727.2 C728.2 C761.2 C869.2 C870.2 C873.2 C874.2 C875.2 C876.2 C877.2 C878.2 C879.2 C880.2 C1590.2 C1793.2 C1838.2 C1839.2 C1840.2 C1841.2 C1842.2 C1846.2 C1847.2 C1848.2 C1849.2 C1850.2 C1851.2 C1852.2 C1853.2 C1854.2 C1855.2 C1856.2 C1857.2 C1858.2 C1859.2 C1860.2 C1863.2 C1864.2 C1865.2 C1866.2 C1869.2 C1870.2 C1871.2 C1872.2 C1875.2 C1876.2 C1877.2 C1878.2 C1879.2 C1880.2 C1940.2 C1941.2 C1942.2 C1943.2 C1944.2 C1945.2 C2839.2 C3016.2 C3017.2 C3022.2 C3024.2 C3058.2 C3059.2 C3060.2 J28.A1(GND_1) J28.A4(GND_2) J28.A5(GND_3) J28.A8(GND_4) J28.A9(GND_5) J28.A12(GND_6) J28.A13(GND_7) J28.A16(GND_8) J28.A17(GND_9) J28.A20(GND_10) J28.A21(GND_11) J28.A24(GND_12) J28.A25(GND_13) J28.A28(GND_14) J28.A29(GND_15) J28.A32(GND_16) J28.A33(GND_17) J28.A36(GND_18) J28.A37(GND_19) J28.A40(GND_20) J28.B2(GND_21) J28.B3(GND_22) J28.B6(GND_23) J28.B7(GND_24) J28.B10(GND_25) J28.B11(GND_26) J28.B14(GND_27) J28.B15(GND_28) J28.B18(GND_29) J28.B19(GND_30) J28.B22(GND_31) J28.B23(GND_32) J28.B26(GND_33) J28.B27(GND_34) J28.B30(GND_35) J28.B31(GND_36) J28.B34(GND_37) J28.B35(GND_38) J28.B38(GND_39) J28.B39(GND_40) J28.C1(GND_41) J28.C4(GND_42) J28.C5(GND_43) J28.C8(GND_44) J28.C9(GND_45) J28.C12(GND_46) J28.C13(GND_47) J28.C16(GND_48) J28.C17(GND_49) J28.C20(GND_50) J28.C21(GND_51) J28.C24(GND_52) J28.C25(GND_53) J28.C28(GND_54) J28.C29(GND_55) J28.C32(GND_56) J28.C33(GND_57) J28.C36(GND_58) J28.C38(GND_59) J28.C40(GND_60) J28.D2(GND_61) J28.D3(GND_62) J28.D6(GND_63) J28.D7(GND_64) J28.D10(GND_65) J28.D13(GND_66) J28.D16(GND_67) J28.D19(GND_68) J28.D22(GND_69) J28.D25(GND_70) J28.D28(GND_71) J28.D37(GND_72) J28.D39(GND_73) J28.E1(GND_74) J28.E4(GND_75) J28.E5(GND_76) J28.E8(GND_77) J28.E11(GND_78) J28.E14(GND_79) J28.E17(GND_80) J28.E20(GND_81) J28.E23(GND_82) J28.E26(GND_83) J28.E29(GND_84) J28.E32(GND_85) J28.E35(GND_86) J28.E38(GND_87) J28.E40(GND_88) J28.F2(GND_89) J28.F3(GND_90) J28.F6(GND_91) J28.F9(GND_92) J28.F12(GND_93) J28.F15(GND_94) J28.F18(GND_95) J28.F21(GND_96) J28.F24(GND_97) J28.F27(GND_98) J28.F30(GND_99) J28.F33(GND_100) J28.F36(GND_101) J28.F39(GND_102) J28.G1(GND_103) J28.G4(GND_104) J28.G5(GND_105) J28.G8(GND_106) J28.G11(GND_107) J28.G14(GND_108) J28.G17(GND_109) J28.G20(GND_110) J28.G23(GND_111) J28.G26(GND_112) J28.G29(GND_113) J28.G32(GND_114) J28.G35(GND_115) J28.G38(GND_116) J28.G40(GND_117) J28.H3(GND_118) J28.H6(GND_119) J28.H9(GND_120) J28.H12(GND_121) J28.H15(GND_122) J28.H18(GND_123) J28.H21(GND_124) J28.H24(GND_125) J28.H27(GND_126) J28.H30(GND_127) J28.H33(GND_128) J28.H36(GND_129) J28.H39(GND_130) J28.J1(GND_131) J28.J4(GND_132) J28.J5(GND_133) J28.J8(GND_134) J28.J11(GND_135) J28.J14(GND_136) J28.J17(GND_137) J28.J20(GND_138) J28.J23(GND_139) J28.J26(GND_140) J28.J29(GND_141) J28.J32(GND_142) J28.J35(GND_143) J28.J38(GND_144) J28.J40(GND_145) J28.K2(GND_146) J28.K3(GND_147) J28.K6(GND_148) J28.K9(GND_149) J28.K12(GND_150) J28.K15(GND_151) J28.K18(GND_152) J28.K21(GND_153) J28.K24(GND_154) J28.K27(GND_155) J28.K30(GND_156) J28.K33(GND_157) J28.K36(GND_158) J28.K39(GND_159) J28.L2(GND_180) J28.L3(GND_181) J28.L6(GND_182) J28.L7(GND_183) J28.L10(GND_184) J28.L11(GND_185) J28.L14(GND_186) J28.L15(GND_187) J28.L18(GND_188) J28.L19(GND_189) J28.L22(GND_190) J28.L23(GND_191) J28.L26(GND_192) J28.L27(GND_193) J28.L30(GND_194) J28.L31(GND_195) J28.L34(GND_196) J28.L35(GND_197) J28.L38(GND_198) J28.L39(GND_199) J28.M1(GND_160) J28.M4(GND_161) J28.M5(GND_162) J28.M8(GND_163) J28.M9(GND_164) J28.M12(GND_165) J28.M13(GND_166) J28.M16(GND_167) J28.M17(GND_168) J28.M20(GND_169) J28.M21(GND_170) J28.M24(GND_171) J28.M25(GND_172) J28.M28(GND_173) J28.M29(GND_174) J28.M32(GND_175) J28.M33(GND_176) J28.M36(GND_177) J28.M37(GND_178) J28.M40(GND_179) J28.Y1(GND_200) J28.Y4(GND_201) J28.Y5(GND_202) J28.Y8(GND_203) J28.Y9(GND_204) J28.Y12(GND_205) J28.Y13(GND_206) J28.Y16(GND_207) J28.Y17(GND_208) J28.Y20(GND_209) J28.Y21(GND_210) J28.Y24(GND_211) J28.Y25(GND_212) J28.Y28(GND_213) J28.Y29(GND_214) J28.Y32(GND_215) J28.Y33(GND_216) J28.Y36(GND_217) J28.Y37(GND_218) J28.Y40(GND_219) J28.Z2(GND_220) J28.Z3(GND_221) J28.Z6(GND_222) J28.Z7(GND_223) J28.Z10(GND_224) J28.Z11(GND_225) J28.Z14(GND_226) J28.Z15(GND_227) J28.Z18(GND_228) J28.Z19(GND_229) J28.Z22(GND_230) J28.Z23(GND_231) J28.Z26(GND_232) J28.Z27(GND_233) J28.Z30(GND_234) J28.Z31(GND_235) J28.Z34(GND_236) J28.Z35(GND_237) J28.Z38(GND_238) J28.Z39(GND_239) J29.21(CAGEGND21) J29.22(CAGEGND22) J29.23(CAGEGND23) J29.24(CAGEGND24) J29.25(CAGEGND25) J29.26(CAGEGND26) J29.27(CAGEGND27) J29.28(CAGEGND28) J29.29(CAGEGND29) J29.30(CAGEGND30) J29.31(CAGEGND31) J29.32(CAGEGND32) J29.33(CAGEGND33) J29.34(CAGEGND34) J29.35(CAGEGND35) J29.36(CAGEGND36) J29.37(CAGEGND37) J29.38(CAGEGND38) J29.39(CAGEGND39) J29.40(CAGEGND40) J29.41(CAGEGND41) J29.42(CAGEGND42) J29.43(CAGEGND43) J29.44(CAGEGND44) J29.45(CAGEGND45) J29.46(CAGEGND46) J29.47(CAGEGND47) J29.48(CAGEGND48) J29.49(CAGEGND49) J29.50(CAGEGND50) J29.51(CAGEGND51) J29.52(CAGEGND52) J29.53(CAGEGND53) J29.54(CAGEGND54) J29.55(CAGEGND55) J29.56(CAGEGND56) J29.57(CAGEGND57) J29.58(CAGEGND58) J29.59(CAGEGND59) J29.LL1(LL1_VEET) J29.LL10(LL10_VEER) J29.LL11(LL11_VEER) J29.LL14(LL14_VEER) J29.LL17(LL17_VEET) J29.LL20(LL20_VEET) J29.LT1(LT1_VEET) J29.LT10(LT10_VEER) J29.LT11(LT11_VEER) J29.LT14(LT14_VEER) J29.LT17(LT17_VEET) J29.LT20(LT20_VEET) J29.RL1(RL1_VEET) J29.RL10(RL10_VEER) J29.RL11(RL11_VEER) J29.RL14(RL14_VEER) J29.RL17(RL17_VEET) J29.RL20(RL20_VEET) J29.RT1(RT1_VEET) J29.RT10(RT10_VEER) J29.RT11(RT11_VEER) J29.RT14(RT14_VEER) J29.RT17(RT17_VEET) J29.RT20(RT20_VEET) J32.2(P2) J35.2(P2) J39.2(P2) J44.2(P2) J123.18(P18) J140.3(P3) J142.17(P17) Q4.2(SOURCE) Q5.2(SOURCE) Q6.2(SOURCE) Q7.2(SOURCE) Q37.2(SOURCE) Q38.2(SOURCE) R260.2 R261.2 R264.2 R269.2 R272.2 R273.2 R274.2 R281.2 R282.2 R283.2 R290.2 R291.2 R292.2 R297.2 R980.2 R981.2 R1039.2 U409.C3(VSS) U409.C5(VSS) U409.C7(VSS) U409.C10(VSS) U409.D3(VSS) U409.D5(VSS) U409.D6(VSS) U409.D10(VSS) U409.E3(VSS) U409.E6(VSS) U409.E7(VSS) U409.E8(VSS) U409.E9(VSS) U409.F3(VSS) U409.F4(VSS) U409.F5(VSS) U409.F6(VSS) U409.F8(VSS) U409.F10(VSS) U409.G4(VSSD) U409.G6(VSS) U409.G8(VSS) U409.G10(VSS) U409.H4(VSSD) U409.H6(VSS) U409.H7(VSS) U409.H8(VSS) U409.H9(VSS) U409.J3(VSS) U409.J6(VSS) U409.J10(VSS) U409.K3(VSS) U409.K5(VSS) U409.K7(VSS) U409.K10(VSS) U409.L5(VSS) U412.4(VSS) U412.7(WP) U414.2(GND) U415.3(GND) U460.1(GND) X7.2(GND2) X7.4(GND4) ; also on sheet 3 4 5 7 8 9 10 11 12 13 14 16 17 18 19 20 21 22 23 24 25 26 27 28 36 37 38 39 40 41 42 43 44 45 46 47 48 49 50 51 52 53 54 55 56 57 58 59 60 61 62 63 64 65 66 67 68 69 70 71 72
VCC1V8_BUS: C1590.1 C1793.1 C3058.1 J142.2(P2) R977.1 R978.1 R979.1 R1761.1 R1762.1 U412.8(VCC) U415.5(VCC) U460.2(VREF1) ; also on sheet 4 9 10 12 20 21 22 23 24 25 26 27 36 37 38 39 42 52 61 62 64
VCC1V8_PGOOD: U415.2(B) ; also on sheet 49 52 60
VCC12_SW: J28.L36(12P0V_3) J28.L37(12P0V_4) J28.L40(12P0V_5) ; also on sheet 28 43 44 45 47 48 49 50 51 52 57 58 62
VDDO_Q4: U409.K12(VDDO_Q4)
VDDO_Q6: U409.K9(VDDO_Q6)
VDDO_Q10: U409.H10(VDDO_Q10)
8A34001_CLK4_IN_N: J28.L25(REFCLK_M2C_N) ; also on sheet 38
8A34001_CLK4_IN_P: J28.L24(REFCLK_M2C_P) ; also on sheet 38
8A34001_EXP_RST_B: U415.1(A) ; also on sheet 22
8A34001_GPIO_0: J142.1(P1) U409.A10(GPIO_DC0)
8A34001_GPIO_1: J142.3(P3) U409.F11(GPIO_DC1)
8A34001_GPIO_2: J142.5(P5) U409.F12(GPIO_DC2)
8A34001_GPIO_3: J142.7(P7) U409.J11(GPIO_DC3)
8A34001_GPIO_4: J142.9(P9) U409.B10(GPIO_DC4)
8A34001_GPIO_5: J142.11(P11) U409.D11(GPIO_DC5)
8A34001_GPIO_6: J142.13(P13) U409.D12(GPIO_DC6)
8A34001_GPIO_7: J142.15(P15) U409.G11(GPIO_DC7)
8A34001_GPIO_8: J142.4(P4) R1052.2 U409.G12(GPIO_DC8)
8A34001_GPIO_9: J142.6(P6) R1038.2 U409.J12(GPIO_DC9)
8A34001_GPIO_10: J142.8(P8) U409.M5(GPIO_DC10)
8A34001_GPIO_11: J142.10(P10) U409.A3(GPIO_DC11)
8A34001_GPIO_12: J142.12(P12) U409.B5(GPIO_DC12)
8A34001_GPIO_13: J142.14(P14) U409.A5(GPIO_DC13)
8A34001_GPIO_14: J142.16(P16) U409.B7(GPIO_DC14)
8A34001_GPIO_15: J142.18(P18) U409.A7(GPIO_DC15)
8A34001_OCXO_TCXO_VDD: C2839.1 L137.2 ; also on sheet 71
8A34001_OCXO_VCC: C3016.1 C3022.1 L137.1 U414.4(VCC)
8A34001_OSCI: C3024.1 U409.B4(OSCI) X7.3(X3)
8A34001_OSCO: C3017.1 U409.A4(OSCO) X7.1(X1)
8A34001_PLL_I2C_CS: Q38.3(DRAIN) R1761.2 U409.M3(CS_A0)
8A34001_PLL_I2C_R_CS: J123.4(P4) R1094.1
8A34001_Q8_OUT_N: J28.L17(SYNC_C2M_N) ; also on sheet 38
8A34001_Q8_OUT_P: J28.L16(SYNC_C2M_P) ; also on sheet 38
8A34001_Q9_OUT_N: J28.L21(REFCLK_C2M_N) ; also on sheet 38
8A34001_Q9_OUT_P: J28.L20(REFCLK_C2M_P) ; also on sheet 38
8A34001_RST_B: U409.L10(MR_N) U415.4(Y)
8A34001_SCL: J123.1(P1) R1770.2 U460.6(SCL2)
8A34001_SCL_LS: U409.K2(SCLK) U460.3(SCL1) ; also on sheet 23
8A34001_SDA: J123.2(P2) J123.3(P3) R1771.2 U460.5(SDA2)
8A34001_SDA_LS: U409.L2(SDIO) U460.4(SDA1) ; also on sheet 23
8A34001_VCC_GPIO_DC: C1853.1 R1038.1 R1052.1 R1772.2 U409.J4(VDD_GPIO_DC) ; also on sheet 71
8A34001_VDD_CLK0: C1851.1 C1852.1 U409.G3(VDD_CLK0) ; also on sheet 38 71
8A34001_VDD_CLK1: C1857.1 C1858.1 U409.H3(VDD_CLK1) ; also on sheet 38 71
8A34001_VDD_FOD: C727.1 C728.1 L114.1 L115.1 L116.1 L117.1 L118.1 L119.1 L120.1 L121.1 L144.1 ; also on sheet 72
8A34001_VDD_FOD_0: C701.1 C702.1 L144.2 U409.D9(VDD_FOD_Q0_Q1)
8A34001_VDD_FOD_1: C703.1 C704.1 L114.2 U409.D8(VDD_FOD_Q2_Q3)
8A34001_VDD_FOD_2: C707.1 C708.1 L115.2 U409.J8(VDD_FOD_Q4_Q5)
8A34001_VDD_FOD_3: C709.1 C710.1 L116.2 U409.J9(VDD_FOD_Q6_Q7)
8A34001_VDD_FOD_4: C869.1 C870.1 L117.2 U409.D7(VDD_FOD_Q8)
8A34001_VDD_FOD_5: C875.1 C876.1 L118.2 U409.F9(VDD_FOD_Q9)
8A34001_VDD_FOD_6: C877.1 C878.1 L119.2 U409.G9(VDD_FOD_Q10)
8A34001_VDD_FOD_7: C879.1 C880.1 L120.2 U409.J7(VDD_FOD_Q11)
8A34001_VDD_FOD_8: C873.1 C874.1 L121.2 U409.E5(VDDA_FBDIV)
8A34001_VDDA: C1846.1 C1847.1 L142.1 L143.1 ; also on sheet 71
8A34001_VDDA_0: C1848.1 C1849.1 C1850.1 L142.2 U409.D4(VDDA_XTAL) U409.E4(VDDA_PDCP)
8A34001_VDDA_1: C1854.1 C1855.1 C1856.1 L143.2 U409.J5(VDDA_BANDGAP) U409.K4(VDDA_LC)
8A34001_VDDD: C1838.1 C1839.1 C1840.1 C1841.1 C1842.1 U409.F7(VDD_DIA_TOP) U409.G5(VDDD) U409.G7(VDD_DIA_BOTTOM) U409.H5(VDDD) ; also on sheet 72
8A34001_VDDO_Q0: C1875.1 C1876.1 L150.2 U409.C8(VDDO_Q0)
8A34001_VDDO_Q0_5_8_9: C1859.1 C1860.1 L148.1 L150.1 L155.1 L156.1 ; also on sheet 71
8A34001_VDDO_Q1: C1863.1 C1864.1 U409.C9(VDDO_Q1) ; also on sheet 71
8A34001_VDDO_Q2: C1879.1 C1880.1 L151.2 U409.C11(VDDO_Q2)
8A34001_VDDO_Q2_3_7_11: C1877.1 C1878.1 L146.1 L149.1 L151.1 L154.1 ; also on sheet 71
8A34001_VDDO_Q3: C1865.1 C1866.1 L146.2 U409.C12(VDDO_Q3)
8A34001_VDDO_Q5: C1869.1 C1870.1 L148.2 U409.K11(VDDO_Q5)
8A34001_VDDO_Q7: C1871.1 C1872.1 L149.2 U409.K8(VDDO_Q7)
8A34001_VDDO_Q8: C1942.1 C1943.1 L155.2 U409.C6(VDDO_Q8)
8A34001_VDDO_Q9: C1944.1 C1945.1 L156.2 U409.E10(VDDO_Q9)
8A34001_VDDO_Q11: C1940.1 C1941.1 L154.2 U409.K6(VDDO_Q11)
8A34001_VPP_NC: U409.L7(VPP)
8A34001_VREF_NC: U409.M7(VREF_OTP)
8A34001_VREG_XTAL: C761.1 U409.C4(VREG_XTAL)
CAP_REF: C762.2 C763.2 C1593.2 U409.L4(CAP_REF)
EEPROM_SCL_OD: J140.1(P1) R978.2 U409.B3(SCL_M) U412.6(SCL)
EEPROM_SDA_OD: J140.2(P2) R977.2 U409.A2(SDA_M) U412.5(SDA)
FMCP_HSPC_PRSNT_M2C_B: J28.H2(PRSNT_M2C_L) J28.Z1(HSPC_PRSNT_M2C_L) R258.2 R259.2 ; also on sheet 22 28
FMCP_HSPC_VREF_A_M2C: J28.H1(VREF_A_M2C)
MIO27_SFP3_TX_DISABLE_B: Q5.1(GATE) R283.1 ; also on sheet 9
MIO28_SFP2_TX_DISABLE_B: Q4.1(GATE) R272.1 ; also on sheet 9
MIO29_SFP1_TX_DISABLE_B: Q7.1(GATE) R297.1 ; also on sheet 9
MIO30_SFP0_TX_DISABLE_B: Q6.1(GATE) R292.1 ; also on sheet 9
SFP0_IIC_SCL: J29.LT5(LT5_SCL) ; also on sheet 23
SFP0_IIC_SDA: J29.LT4(LT4_SDA) ; also on sheet 23
SFP0_LOS: J29.LT8(LT8_RX_LOS) R289.2 TP13.1(TP)
SFP0_MOD_DETECT: J29.LT6(LT6_MOD_ABS) R288.2 TP12.1(TP)
SFP0_RS0: J29.LT7(LT7_RSO) R262.2 R269.1
SFP0_RS1: J29.LT9(LT9_RS1) R263.2 R264.1
SFP0_RX_N: J29.LT12(LT12_RD-) ; also on sheet 6
SFP0_RX_P: J29.LT13(LT13_RD+) ; also on sheet 6
SFP0_TX_DISABLE: J29.LT3(LT3_TX-DISABLE) J39.1(P1) Q6.3(DRAIN) R287.2
SFP0_TX_FAULT: J29.LT2(LT2_TX-FAULT) R286.2 TP11.1(TP)
SFP0_TX_N: J29.LT19(LT19_TD-) ; also on sheet 6
SFP0_TX_P: J29.LT18(LT18_TD+) ; also on sheet 6
SFP0_VCCR: C353.1 C354.1 J29.LT15(LT15_VCCR) L18.2
SFP0_VCCT: C355.1 C356.1 J29.LT16(LT16_VCCT) L19.2
SFP1_IIC_SCL: J29.LL5(LL5_SCL) ; also on sheet 23
SFP1_IIC_SDA: J29.LL4(LL4_SDA) ; also on sheet 23
SFP1_LOS: J29.LL8(LL8_RX_LOS) R296.2 TP16.1(TP)
SFP1_MOD_DETECT: J29.LL6(LL6_MOD_ABS) R295.2 TP15.1(TP)
SFP1_RS0: J29.LL7(LL7_RSO) R270.2 R273.1
SFP1_RS1: J29.LL9(LL9_RS1) R271.2 R274.1
SFP1_RX_N: J29.LL12(LL12_RD-) ; also on sheet 6
SFP1_RX_P: J29.LL13(LL13_RD+) ; also on sheet 6
SFP1_TX_DISABLE: J29.LL3(LL3_TX-DISABLE) J44.1(P1) Q7.3(DRAIN) R294.2
SFP1_TX_FAULT: J29.LL2(LL2_TX-FAULT) R293.2 TP14.1(TP)
SFP1_TX_N: J29.LL19(LL19_TD-) ; also on sheet 6
SFP1_TX_P: J29.LL18(LL18_TD+) ; also on sheet 6
SFP1_VCCR: C357.1 C358.1 J29.LL15(LL15_VCCR) L20.2
SFP1_VCCT: C359.1 C360.1 J29.LL16(LL16_VCCT) L21.2
SFP2_IIC_SCL: J29.RT5(RT5_SCL) ; also on sheet 23
SFP2_IIC_SDA: J29.RT4(RT4_SDA) ; also on sheet 23
SFP2_LOS: J29.RT8(RT8_RX_LOS) R268.2 TP7.1(TP)
SFP2_MOD_DETECT: J29.RT6(RT6_MOD_ABS) R267.2 TP6.1(TP)
SFP2_RS0: J29.RT7(RT7_RSO) R279.2 R281.1
SFP2_RS1: J29.RT9(RT9_RS1) R280.2 R282.1
SFP2_RX_N: J29.RT12(RT12_RD-) ; also on sheet 6
SFP2_RX_P: J29.RT13(RT13_RD+) ; also on sheet 6
SFP2_TX_DISABLE: J29.RT3(RT3_TX-DISABLE) J32.1(P1) Q4.3(DRAIN) R266.2
SFP2_TX_FAULT: J29.RT2(RT2_TX-FAULT) R265.2 TP5.1(TP)
SFP2_TX_N: J29.RT19(RT19_TD-) ; also on sheet 6
SFP2_TX_P: J29.RT18(RT18_TD+) ; also on sheet 6
SFP2_VCCR: C345.1 C347.1 J29.RT15(RT15_VCCR) L14.2
SFP2_VCCT: C346.1 C348.1 J29.RT16(RT16_VCCT) L15.2
SFP3_IIC_SCL: J29.RL5(RL5_SCL) ; also on sheet 23
SFP3_IIC_SDA: J29.RL4(RL4_SDA) ; also on sheet 23
SFP3_LOS: J29.RL8(RL8_RX_LOS) R278.2 TP10.1(TP)
SFP3_MOD_DETECT: J29.RL6(RL6_MOD_ABS) R277.2 TP9.1(TP)
SFP3_RS0: J29.RL7(RL7_RSO) R284.2 R290.1
SFP3_RS1: J29.RL9(RL9_RS1) R285.2 R291.1
SFP3_RX_N: J29.RL12(RL12_RD-) ; also on sheet 6
SFP3_RX_P: J29.RL13(RL13_RD+) ; also on sheet 6
SFP3_TX_DISABLE: J29.RL3(RL3_TX-DISABLE) J35.1(P1) Q5.3(DRAIN) R276.2
SFP3_TX_FAULT: J29.RL2(RL2_TX-FAULT) R275.2 TP8.1(TP)
SFP3_TX_N: J29.RL19(RL19_TD-) ; also on sheet 6
SFP3_TX_P: J29.RL18(RL18_TD+) ; also on sheet 6
SFP3_VCCR: C349.1 C350.1 J29.RL15(RL15_VCCR) L16.2
SFP3_VCCT: C351.1 C352.1 J29.RL16(RL16_VCCT) L17.2
UTIL_3V3: C344.1 C3059.1 J28.Z40(3P3V_5) L14.1 L15.1 L16.1 L17.1 L18.1 L19.1 L20.1 L21.1 R258.1 R259.1 R262.1 R263.1 R265.1 R266.1 R267.1 R268.1 R270.1 R271.1 R275.1 R276.1 R277.1 R278.1 R279.1 R280.1 R284.1 R285.1 R286.1 R287.1 R288.1 R289.1 R293.1 R294.1 R295.1 R296.1 R1760.1 R1770.1 R1771.1 ; also on sheet 9 10 20 22 23 24 25 26 27 28 29 36 37 40 42 43 44 45 47 49 51 53 54 55 56 57 59 60 61 64
VADJ_FMC: J28.H40(VADJ_4) ; also on sheet 28 29 47
VIO_B_M2C_1_NC: J28.J39(VIO_B_M2C_1)
VIO_B_M2C_2_NC: J28.K40(VIO_B_M2C_2)
VREF_B_M2C_NC: J28.K1(VREF_B_M2C)
N21343085: C343.1 J28.ST1(GND) R261.1
N21343092: C342.1 J28.ST2(GND) R260.1
N26018882: C762.1 C763.1 R456.1 U409.M4(FILTER_PAD)
N26018994: C1593.1 R456.2
N26623755: R1032.1 R1039.1 U414.3(OUT)
N26623759: R1032.2 U409.A1(XO_DPLL)
N30265864: R979.2 U412.3(A2)
N30265920: R980.1 U412.1(A0)
N30265924: R981.1 U412.2(A1)
N31592051: C3060.1 R1760.2 U460.7(VREF2) U460.8(EN)
N31595523: Q37.3(DRAIN) Q38.1(GATE) R1762.2
N32032998: R1772.1 U409.M10(TEST_N)
N33709981: Q37.1(GATE) R1094.2

Not connected (* = marked no-connect by the designer): J28 H4(CLK0_M2C_P)* H5(CLK0_M2C_N)* H7(LA02_P)* H8(LA02_N)* H10(LA04_P)* H11(LA04_N)* H13(LA07_P)* H14(LA07_N)* H16(LA11_P)* H17(LA11_N)* H19(LA15_P)* H20(LA15_N)* H22(LA19_P)* H23(LA19_N)* H25(LA21_P)* H26(LA21_N)* H28(LA24_P)* H29(LA24_N)* H31(LA28_P)* H32(LA28_N)* H34(LA30_P)* H35(LA30_N)* H37(LA32_P)* H38(LA32_N)* J2(CLK3_BIDIR_P)* J3(CLK3_BIDIR_N)* J6(HA03_P)* J7(HA03_N)* J9(HA07_P)* J10(HA07_N)* J12(HA11_P)* J13(HA11_N)* J15(HA14_P)* J16(HA14_N)* J18(HA18_P)* J19(HA18_N)* J21(HA22_P)* J22(HA22_N)* J24(HB01_P)* J25(HB01_N)* J27(HB07_P)* J28(HB07_N)* J30(HB11_P)* J31(HB11_N)* J33(HB15_P)* J34(HB15_N)* J36(HB18_P)* J37(HB18_N)* K4(CLK2_BIDIR_P)* K5(CLK2_BIDIR_N)* K7(HA02_P)* K8(HA02_N)* K10(HA06_P)* K11(HA06_N)* K13(HA10_P)* K14(HA10_N)* K16(HA17_P_CC)* K17(HA17_N_CC)* K19(HA21_P)* K20(HA21_N)* K22(HA23_P)* K23(HA23_N)* K25(HB00_P_CC)* K26(HB00_N_CC)* K28(HB06_P_CC)* K29(HB06_N_CC)* K31(HB10_P)* K32(HB10_N)* K34(HB14_P)* K35(HB14_N)* K37(HB17_P_CC)* K38(HB17_N_CC)* L1(RES1)* L4(GBTCLK4_M2C_P)* L5(GBTCLK4_M2C_N)* L8(GBTCLK3_M2C_P)* L9(GBTCLK3_M2C_N)* L12(GBTCLK2_M2C_P)* L13(GBTCLK2_M2C_N)* L28(SYNC_M2C_P)* L29(SYNC_M2C_N)* L32(RES2)* L33(RES3)* M2(DP23_M2C_P)* M3(DP23_M2C_N)* M6(DP22_M2C_P)* M7(DP22_M2C_N)* M10(DP21_M2C_P)* M11(DP21_M2C_N)* M14(DP20_M2C_P)* M15(DP20_M2C_N)* M18(DP14_C2M_P)* M19(DP14_C2M_N)* M22(DP15_C2M_P)* M23(DP15_C2M_N)* M26(DP16_C2M_P)* M27(DP16_C2M_N)* M30(DP17_C2M_P)* M31(DP17_C2M_N)* M34(DP18_C2M_P)* M35(DP18_C2M_N)* M38(DP19_C2M_P)* M39(DP19_C2M_N)* Y2(DP23_C2M_P)* Y3(DP23_C2M_N)* Y6(DP21_C2M_P)* Y7(DP21_C2M_N)* Y10(DP10_M2C_P)* Y11(DP10_M2C_N)* Y14(DP12_M2C_P)* Y15(DP12_M2C_N)* Y18(DP14_M2C_P)* Y19(DP14_M2C_N)* Y22(DP15_M2C_P)* Y23(DP15_M2C_N)* Y26(DP11_C2M_P)* Y27(DP11_C2M_N)* Y30(DP13_C2M_P)* Y31(DP13_C2M_N)* Y34(DP17_M2C_P)* Y35(DP17_M2C_N)* Y38(DP19_M2C_P)* Y39(DP19_M2C_N)* Z4(DP22_C2M_P)* Z5(DP22_C2M_N)* Z8(DP20_C2M_P)* Z9(DP20_C2M_N)* Z12(DP11_M2C_P)* Z13(DP11_M2C_N)* Z16(DP13_M2C_P)* Z17(DP13_M2C_N)* Z20(GBTCLK5_M2C_P)* Z21(GBTCLK5_M2C_N)* Z24(DP10_C2M_P)* Z25(DP10_C2M_N)* Z28(DP12_C2M_P)* Z29(DP12_C2M_N)* Z32(DP16_M2C_P)* Z33(DP16_M2C_N)* Z36(DP18_M2C_P)* Z37(DP18_M2C_N)*; J123 5(P5)* 6(P6)* 7(P7)* 8(P8)* 9(P9)* 10(P10)* 11(P11)* 12(P12)* 13(P13)* 14(P14)* 15(P15)* 16(P16)* 17(P17)*; U409 K1(SDI_A1_AUX)* L1(SDIO_AUX)* L3(CS_A0_AUX)* M1(SCLK_AUX)* M2(SDI_A1)*; U414 1(NC)*

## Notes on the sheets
sheet 30
- ANSI/VITA 57.4 - Draft OCT 2015
sheet 31
- ANSI/VITA 57.4 - Draft OCT 2015
sheet 32
- ANSI/VITA 57.4 - Draft OCT 2015
sheet 33
- FULL BW RX
- FULL BW TX
- Infineon Bulk
- LOW BW RX
- LOW TW RX
- FULL BW RX
- FULL BW TX
- LOW BW RX
- LOW TW RX
- FULL BW RX
- FULL BW TX
- LOW BW RX
- LOW TW RX
- FULL BW TX
- FULL BW RX
- LOW BW RX
- LOW TW RX
- ZSFP CAGE, 4-PORT 2x2
sheet 34
- 1588 GPIOs 1.8V IO
- Connor-Winfield
  SiCS-043-048.0M
- Place close to 8A34001
- EEPROM Header
